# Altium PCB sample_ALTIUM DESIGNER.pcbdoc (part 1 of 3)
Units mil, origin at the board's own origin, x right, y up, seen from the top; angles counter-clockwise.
Board outline 2485.01 x 1905 mil, 6 copper layers (1 TallParts (2oz), 2 RTNS (2oz), 3 InternalPlane1 (2 oz), 4 InternalPlane2 (2 oz), 5 Signal (2oz), 6 LoParts (2oz)), stack 46.8 mil thick; 176 components, 89 nets, 769 pads, 0 vias.
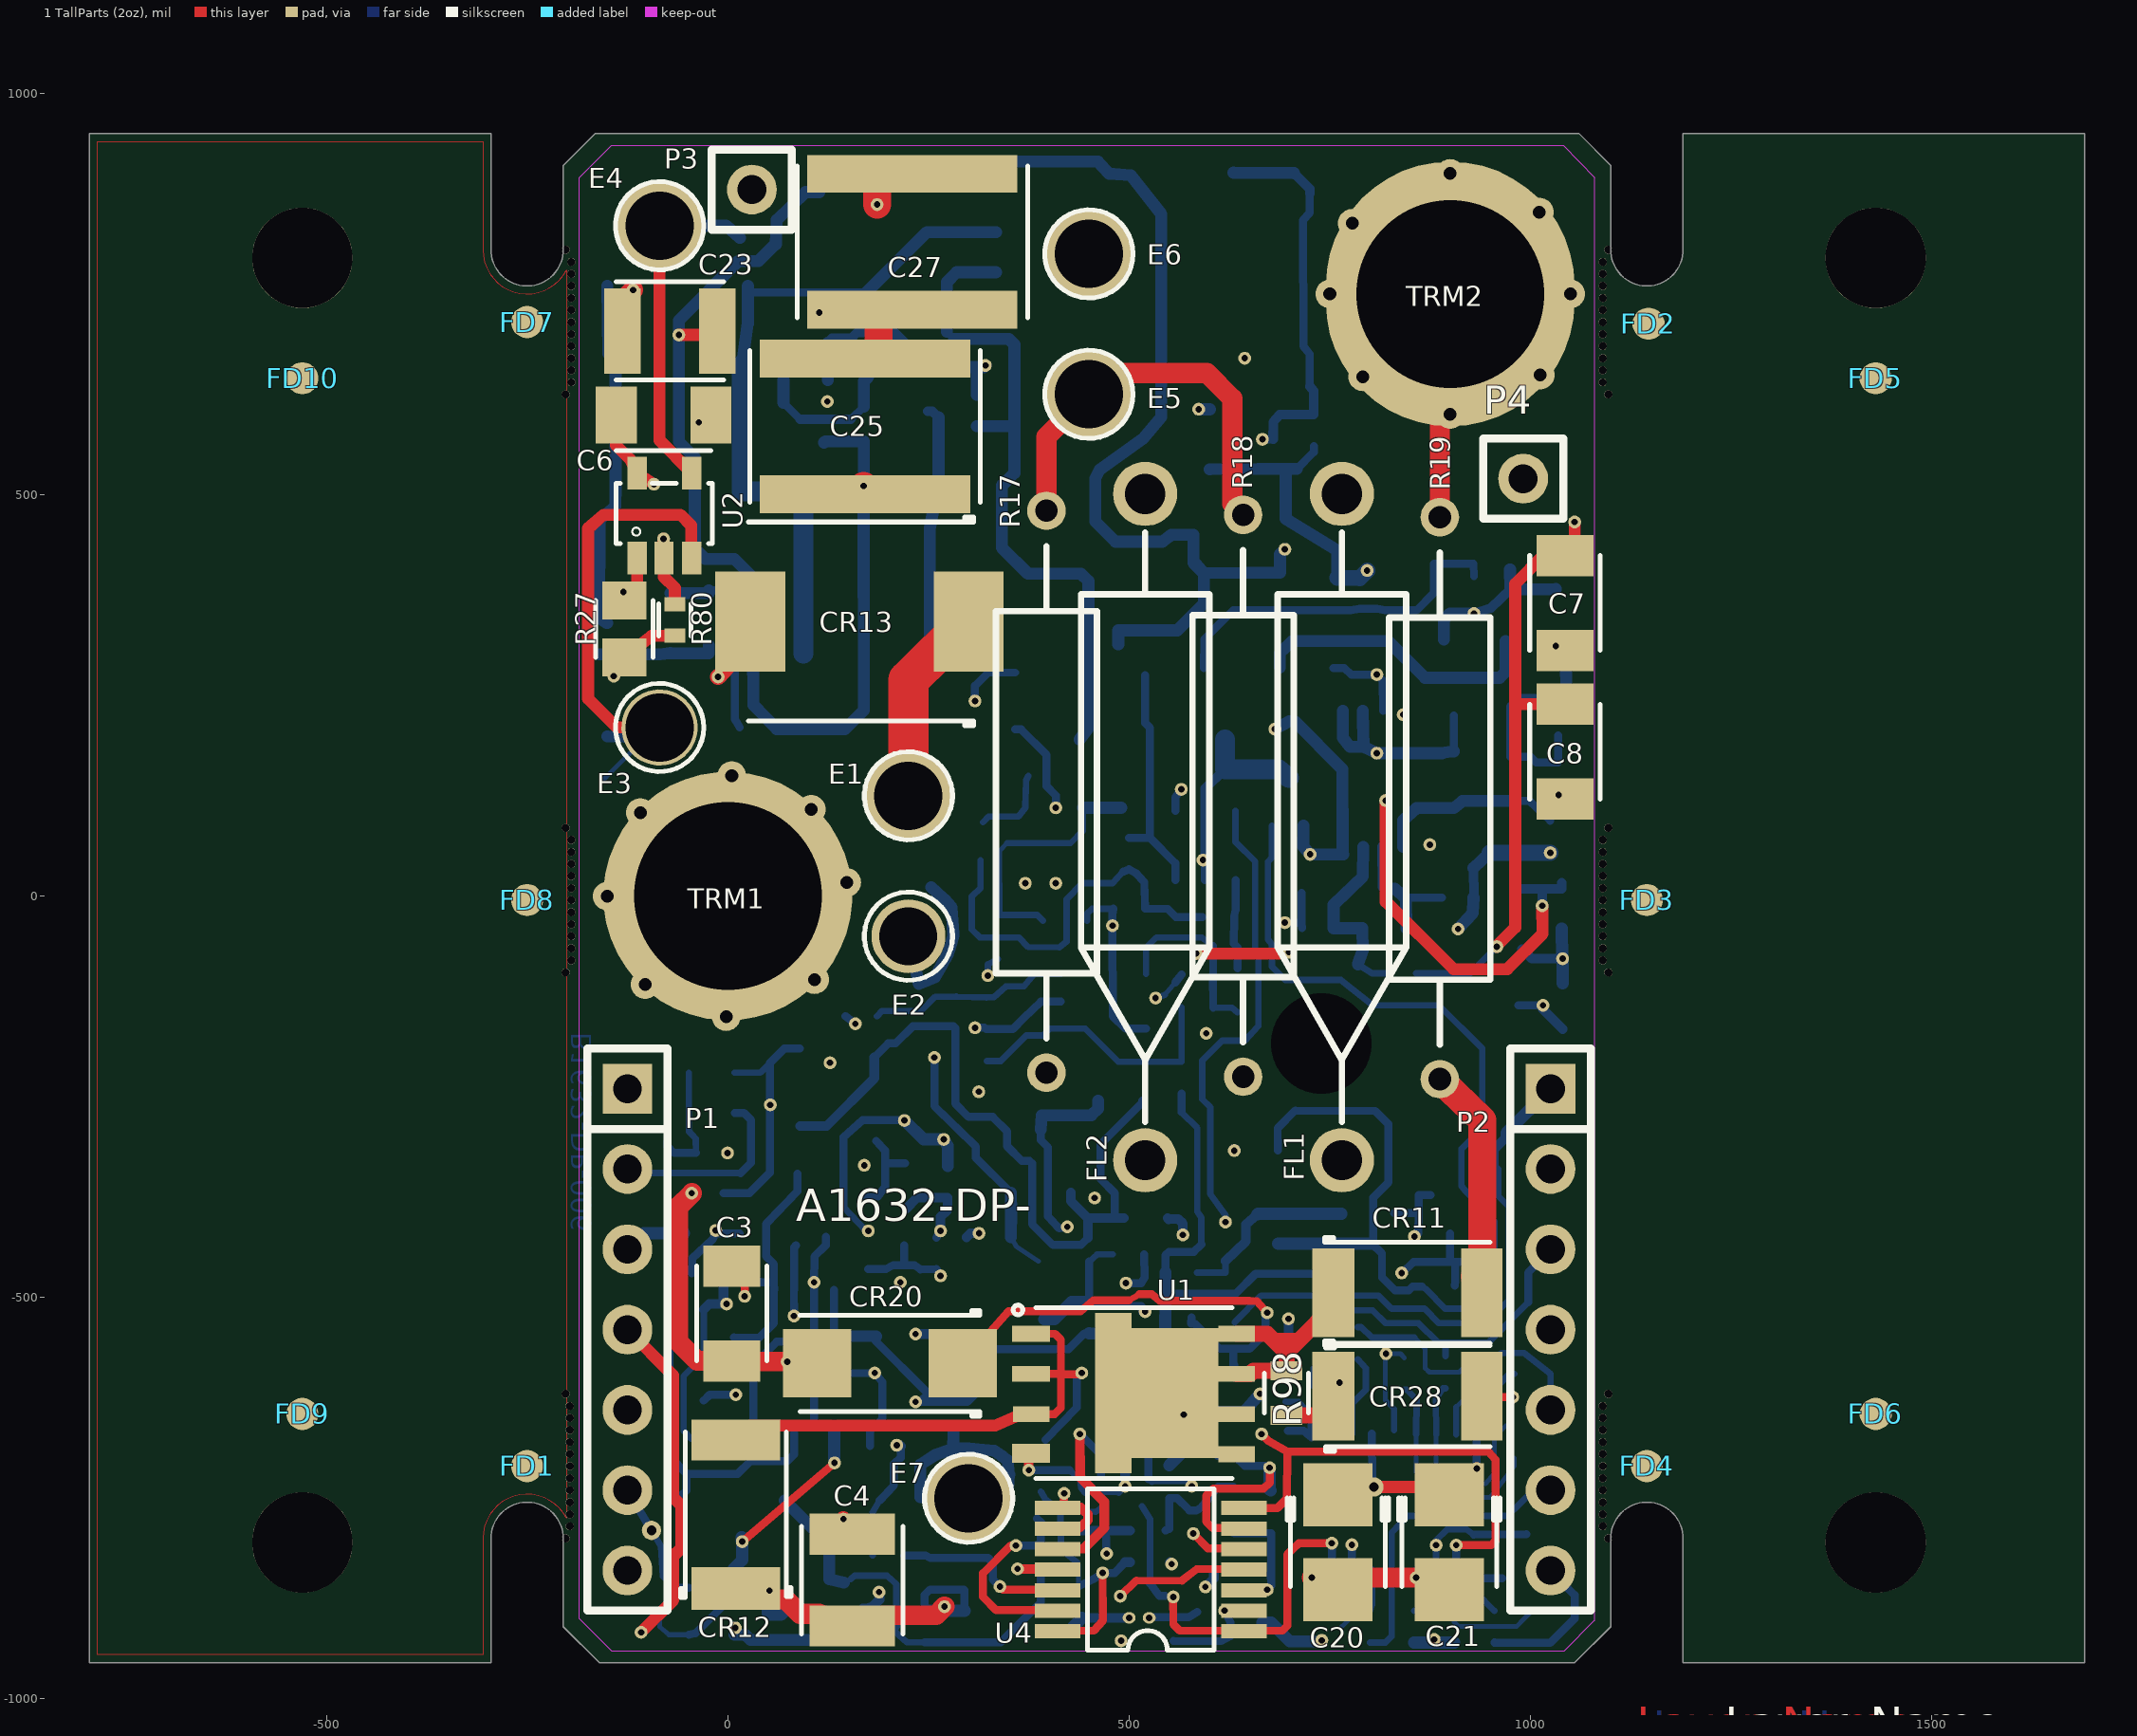
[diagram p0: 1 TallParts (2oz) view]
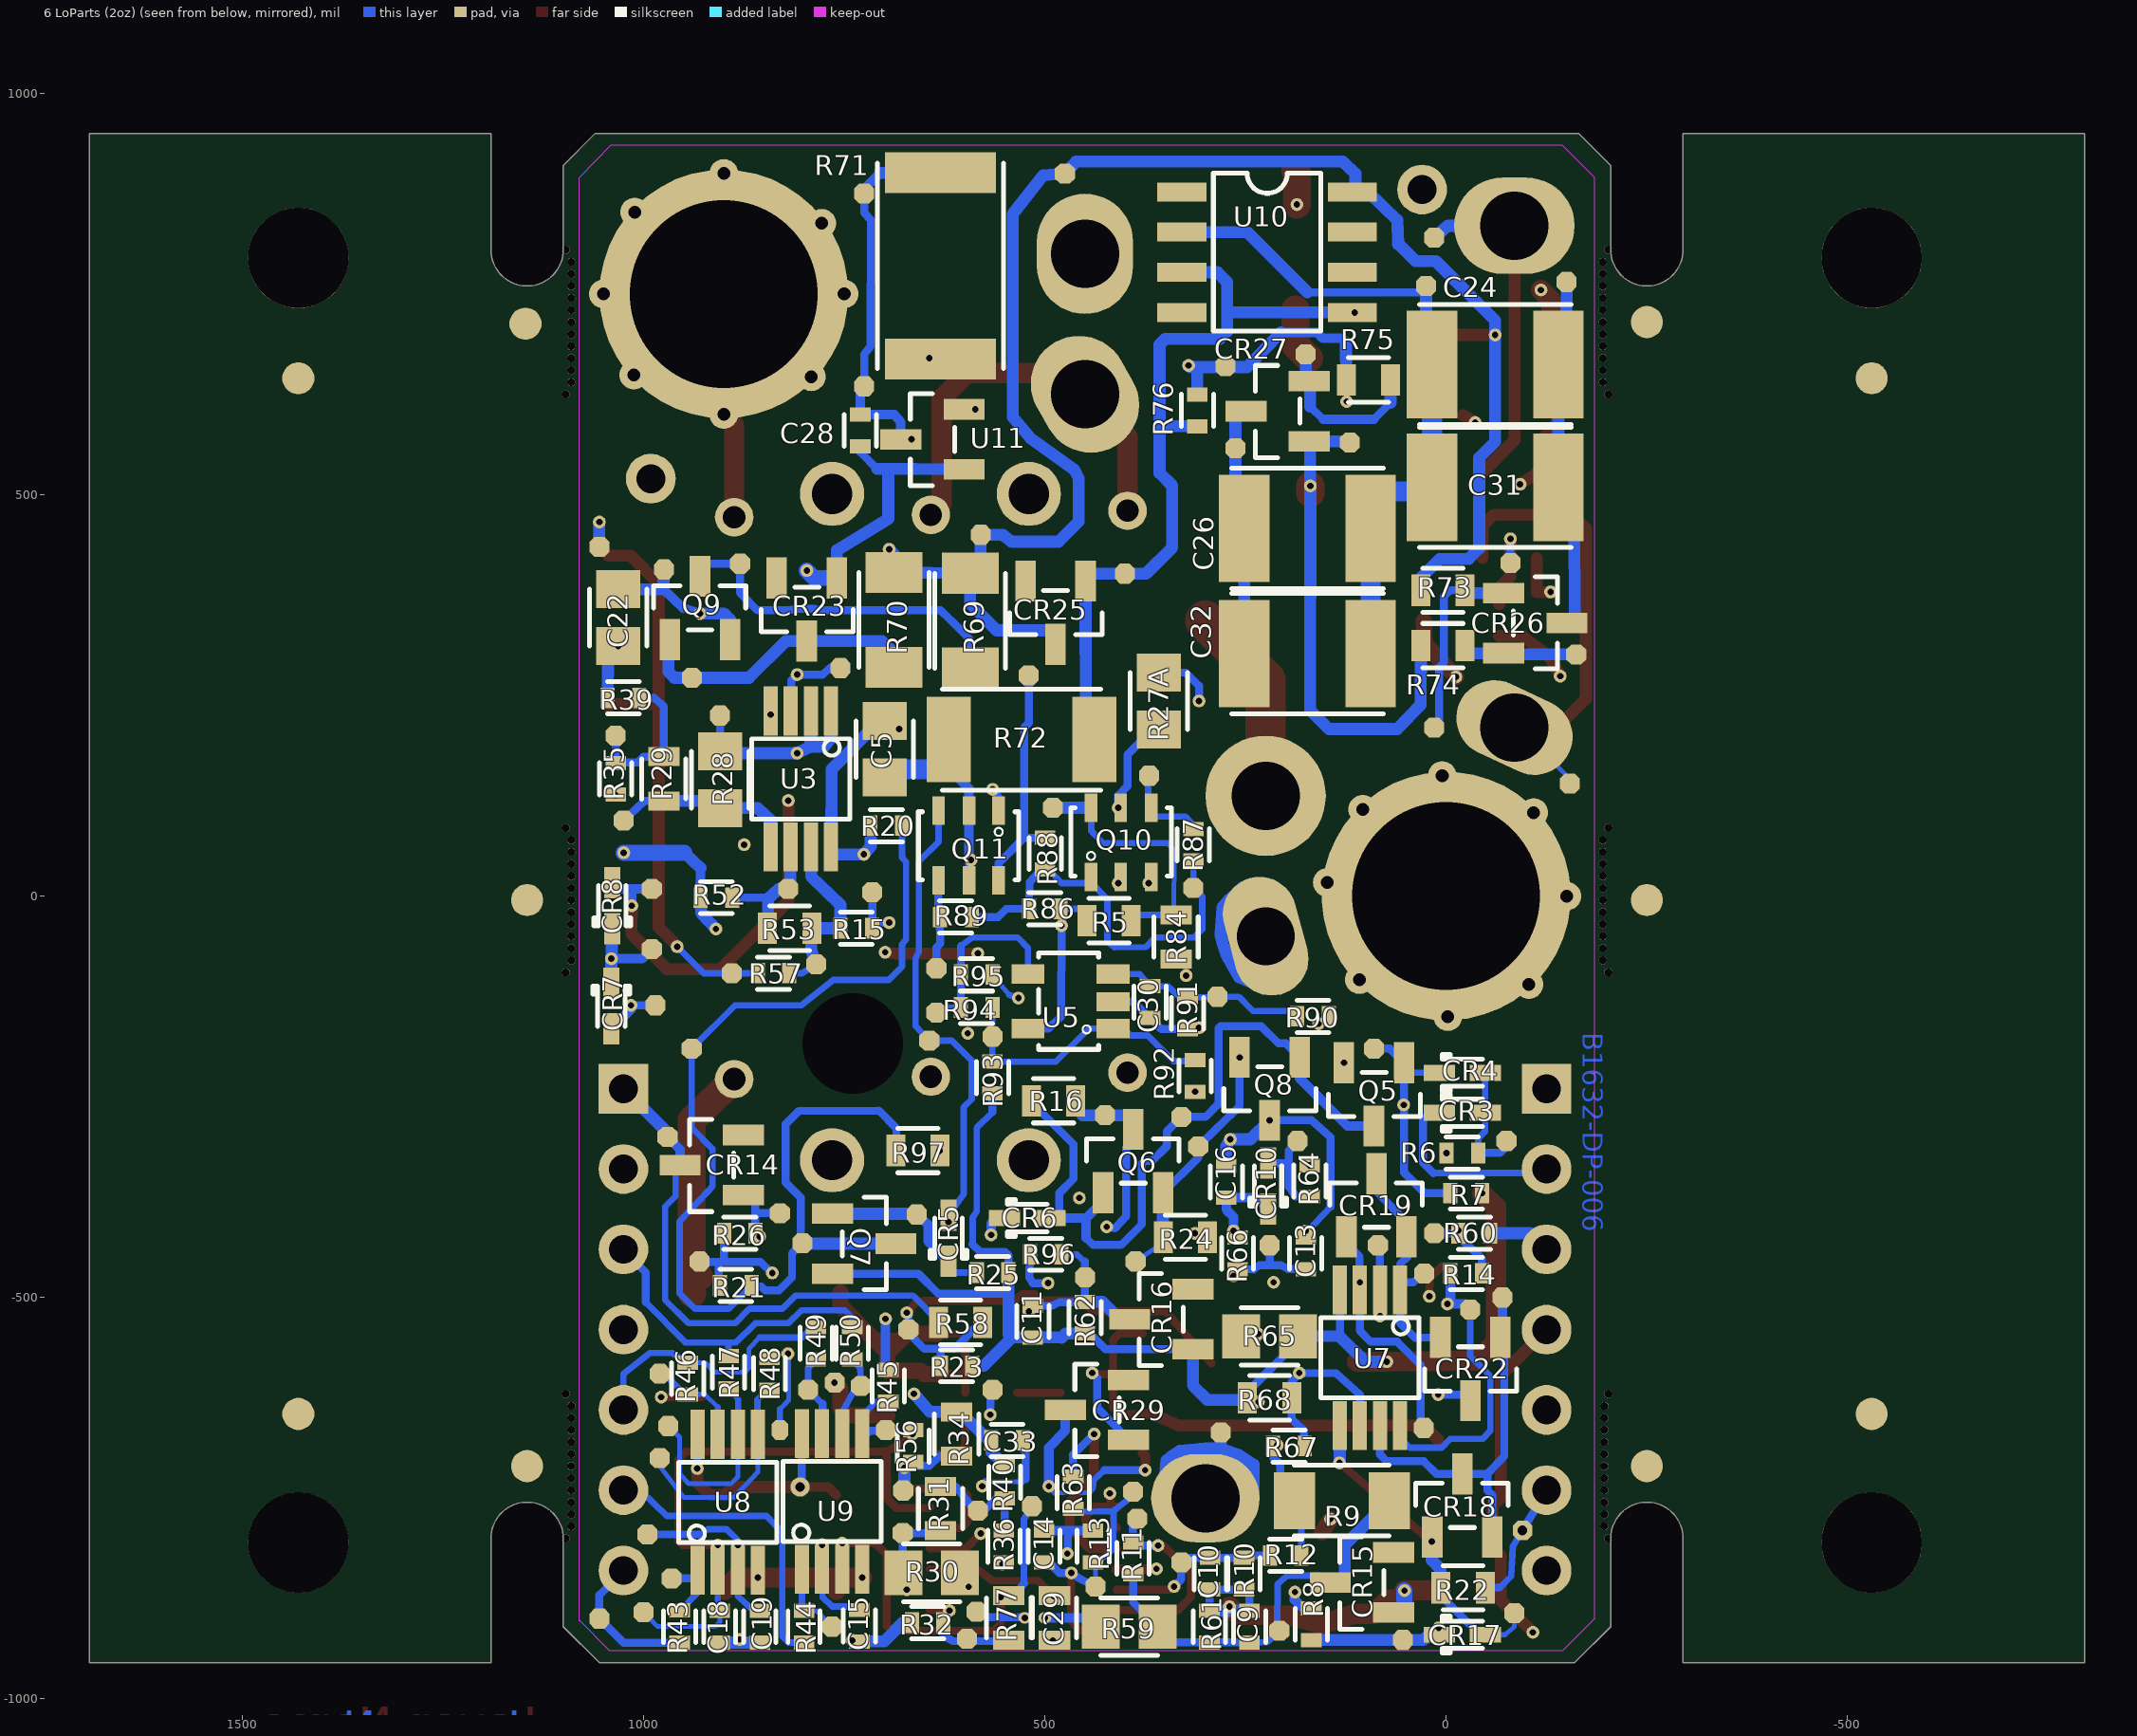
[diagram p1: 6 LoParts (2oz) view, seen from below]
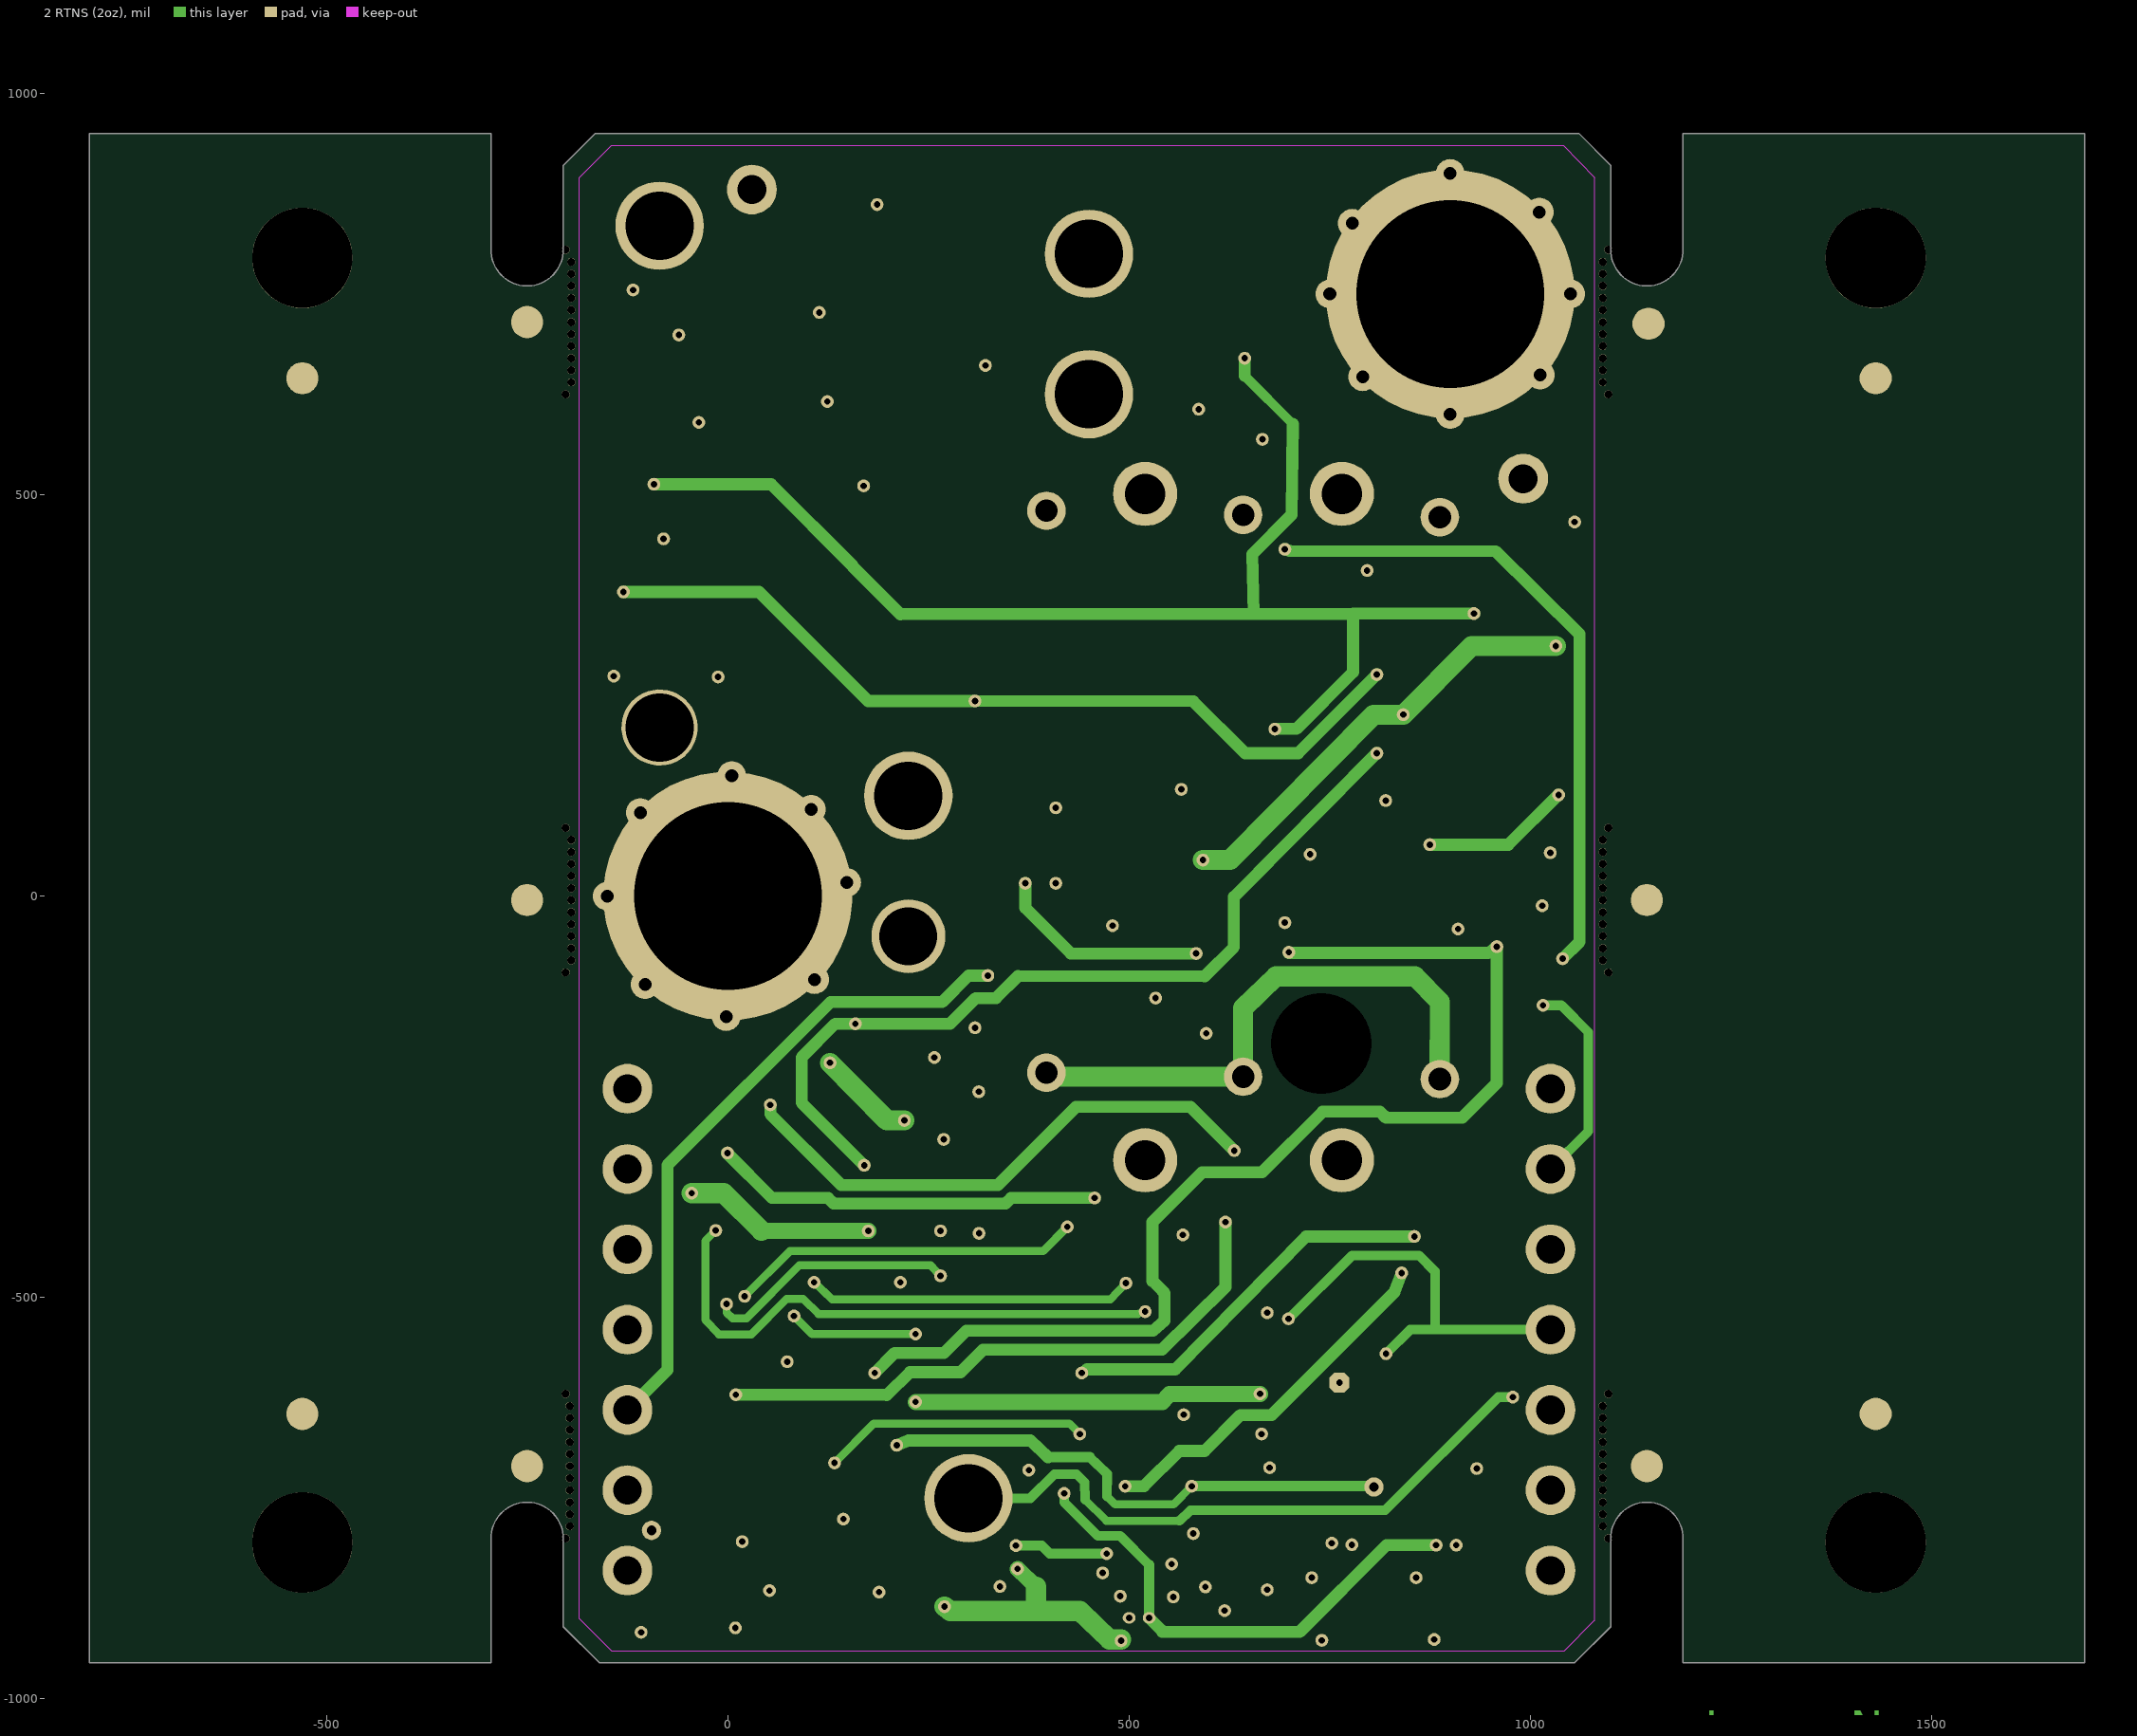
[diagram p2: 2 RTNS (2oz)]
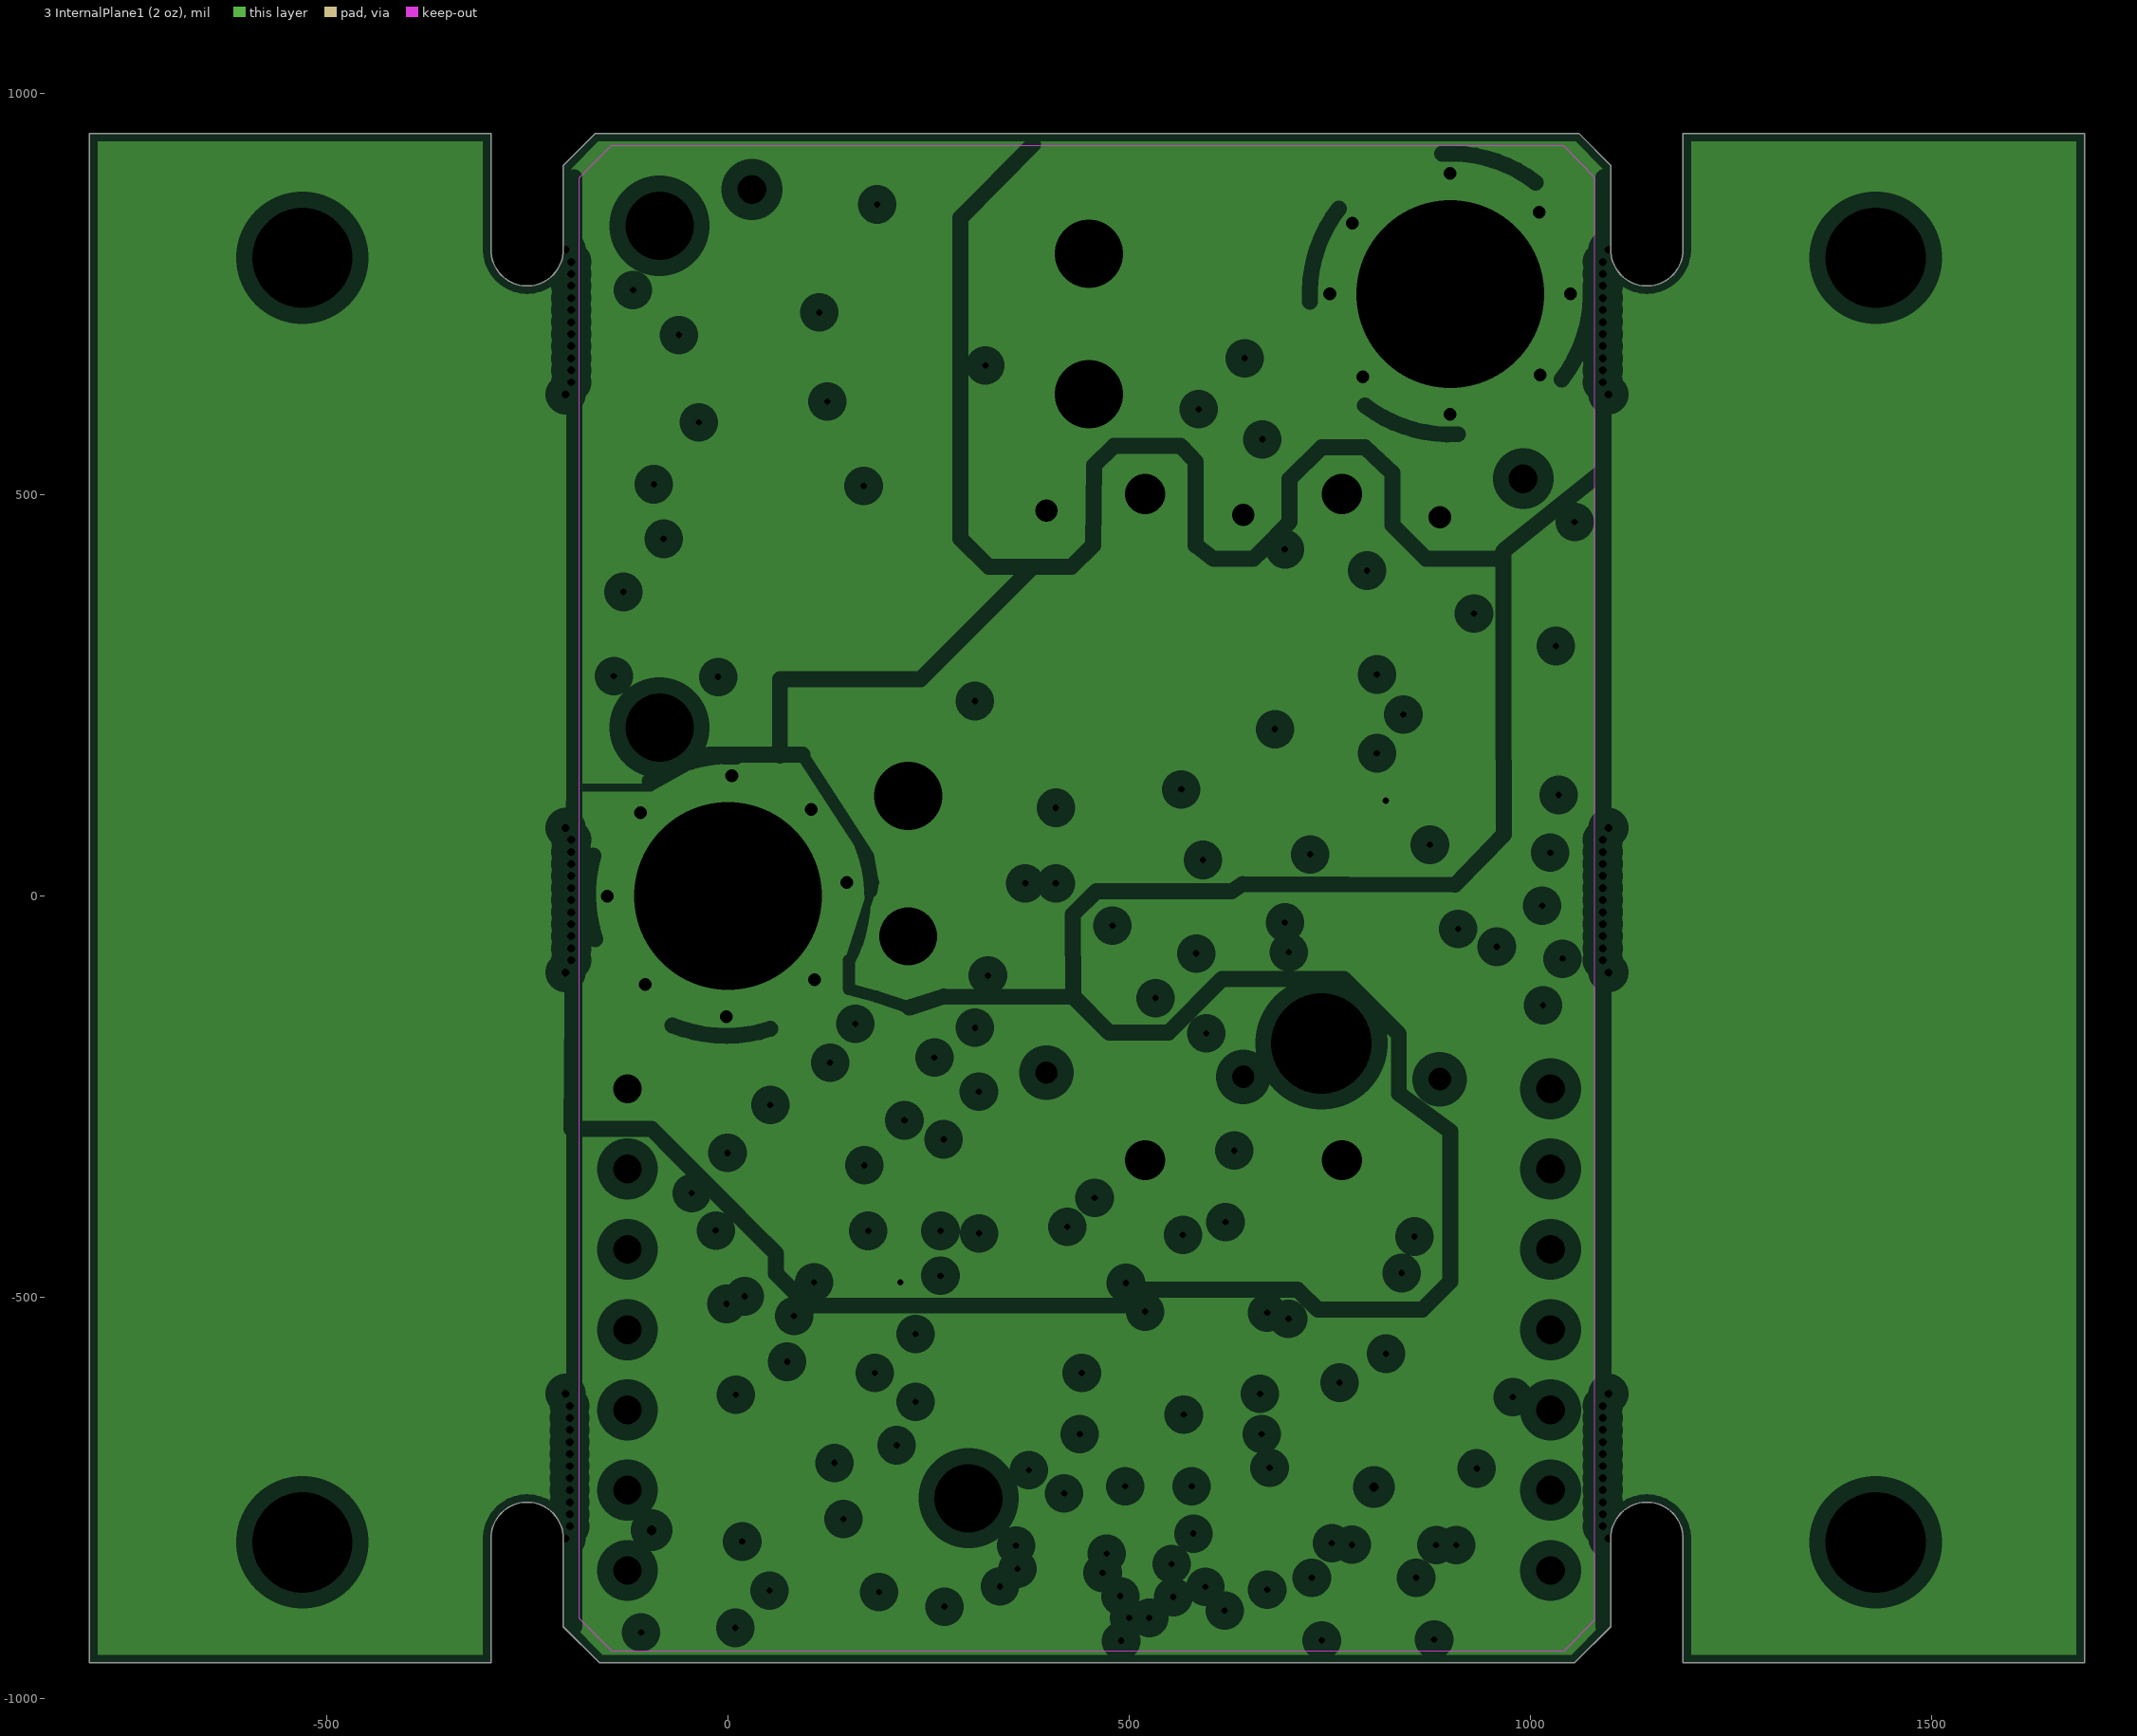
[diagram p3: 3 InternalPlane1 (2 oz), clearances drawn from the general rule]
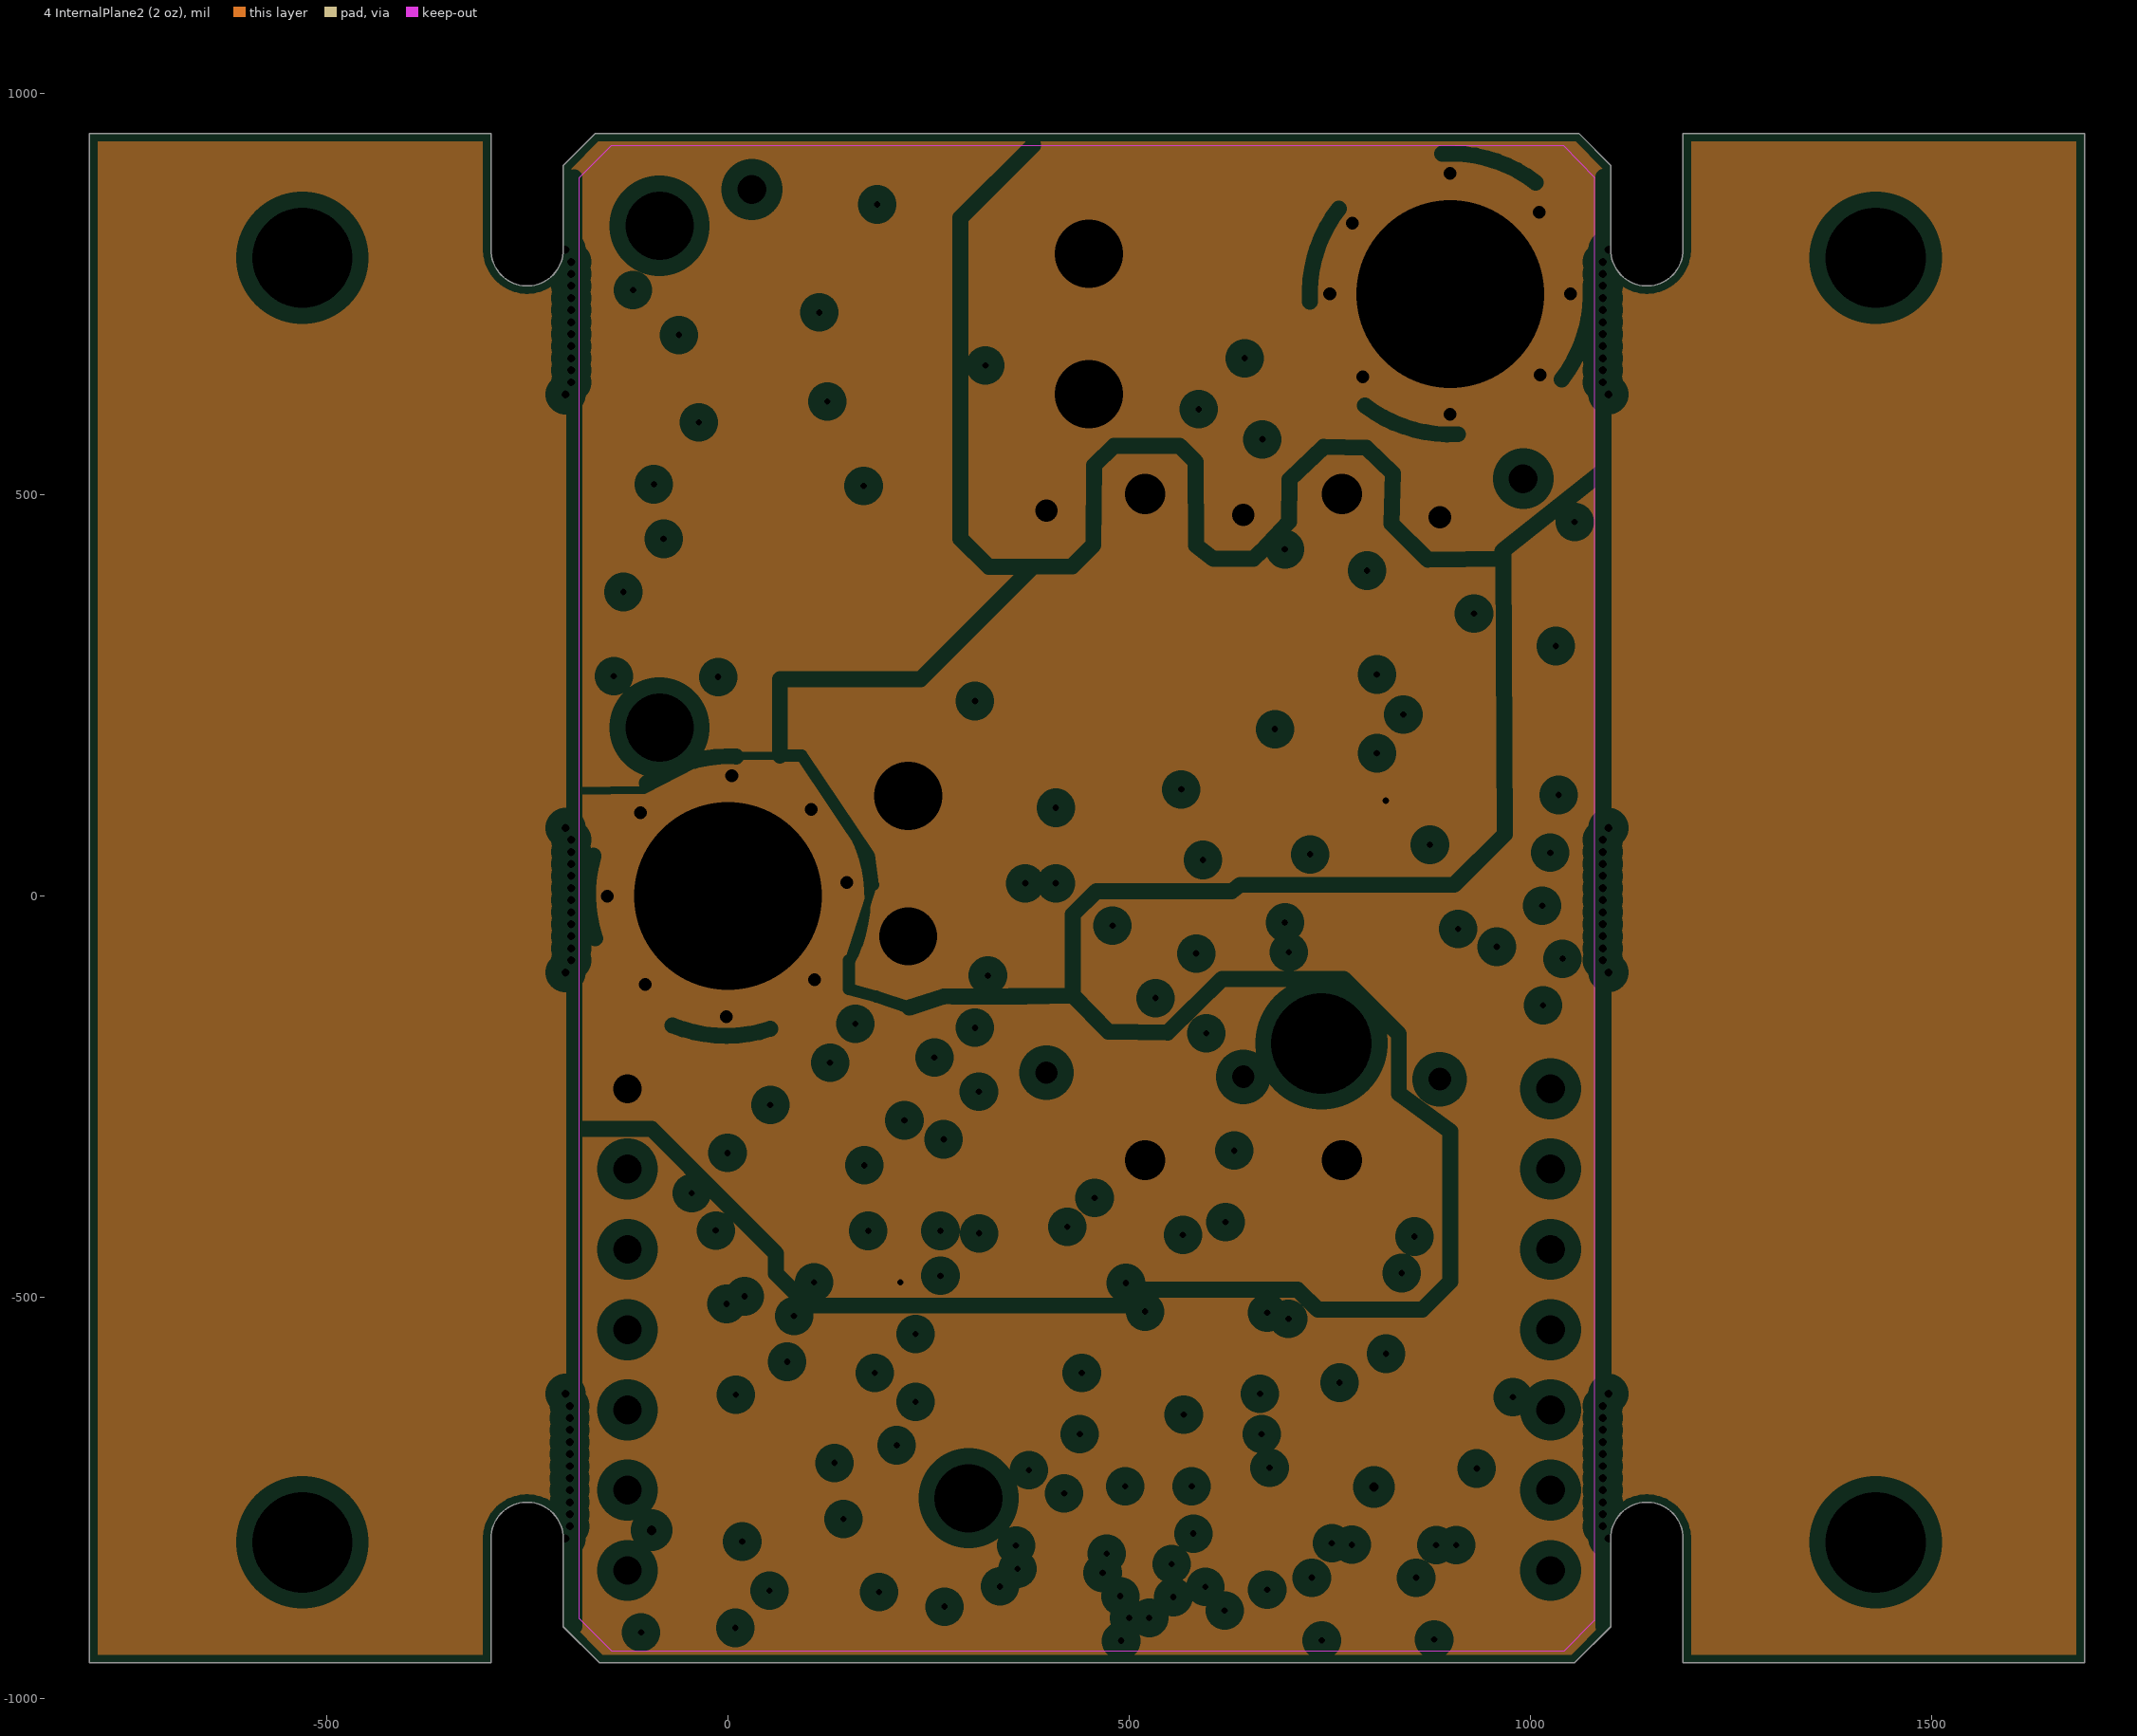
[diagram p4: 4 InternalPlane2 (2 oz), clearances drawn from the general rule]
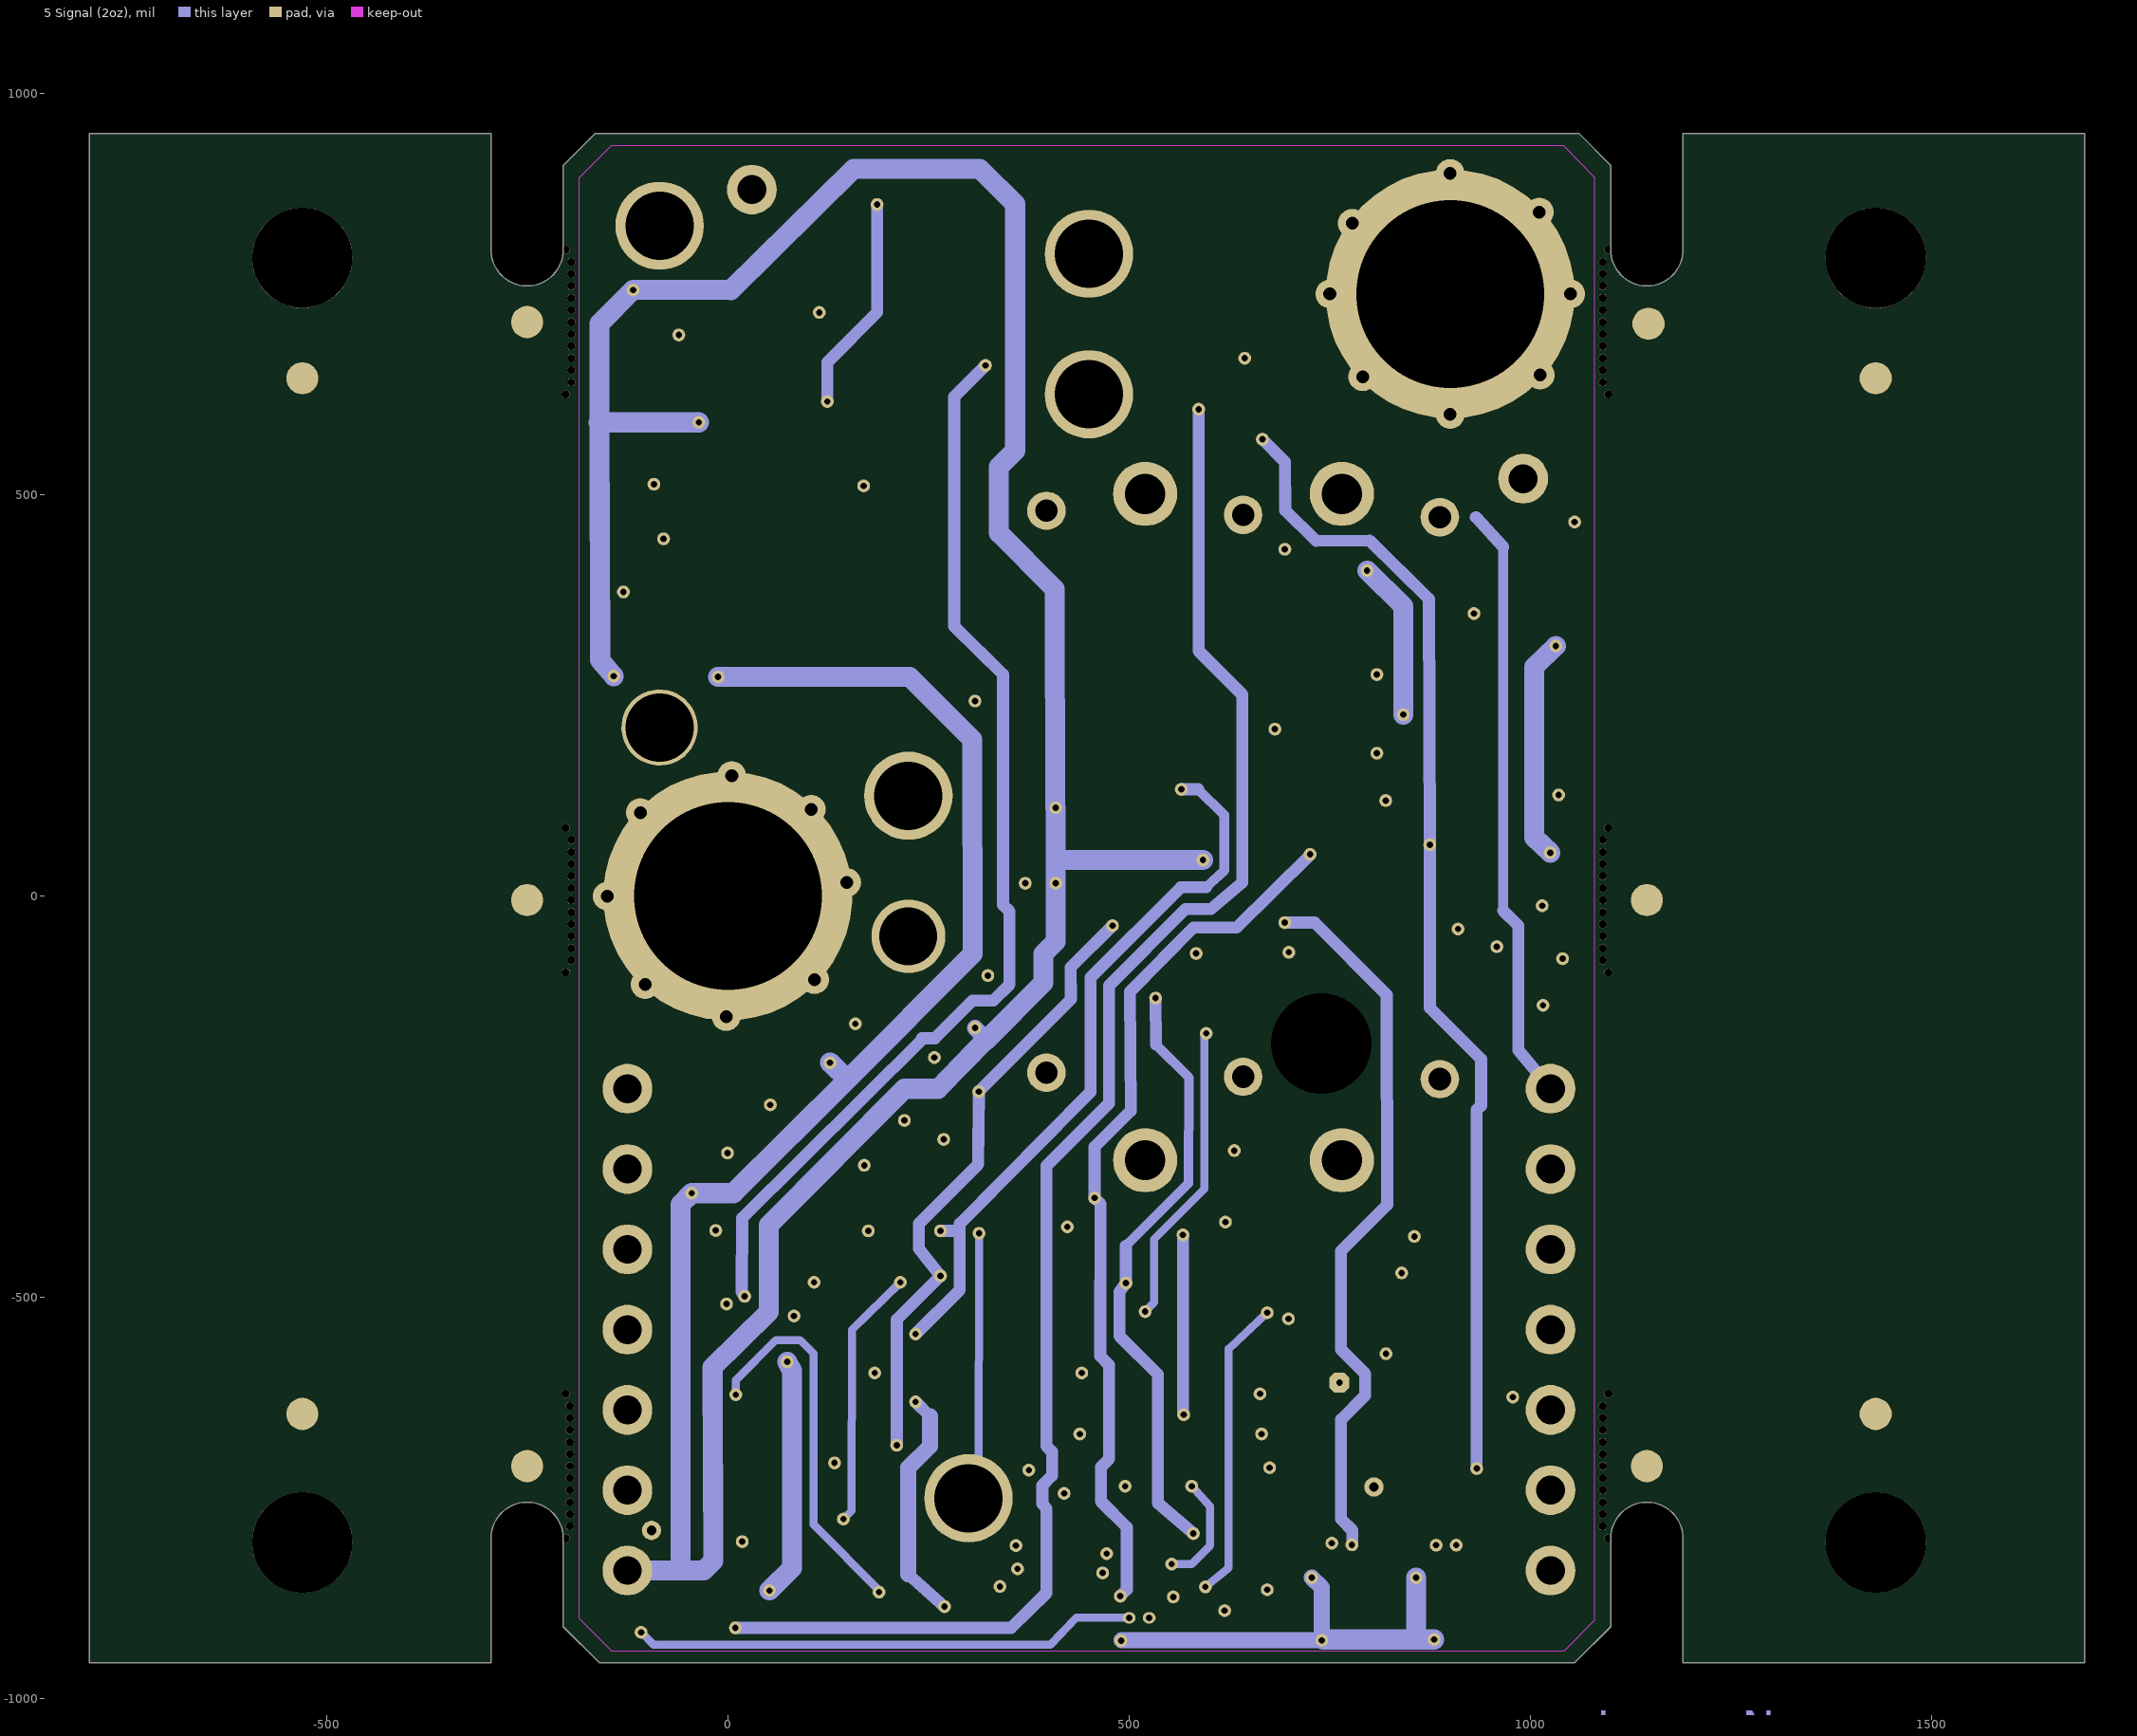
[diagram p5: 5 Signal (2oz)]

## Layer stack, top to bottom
1 TallParts (2oz): signal copper 2.8
Dielectric: core 6, FR-4, Dk 4.8
2 RTNS (2oz): signal copper 2.8
Dielectric: prepreg 6, FR-4, Dk 4.8
3 InternalPlane1 (2 oz): plane copper 2.8, net (Multiple Nets)
Dielectric: core 6, FR-4, Dk 4.8
4 InternalPlane2 (2 oz): plane copper 2.8, net (Multiple Nets)
Dielectric: prepreg 6, FR-4, Dk 4.8
5 Signal (2oz): signal copper 2.8
Dielectric: core 6, FR-4, Dk 4.8
6 LoParts (2oz): signal copper 2.8

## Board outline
-795,-954.96 -295,-954.96 -295,-799.96 cw(c-250,-799.96) -205,-799.96 -204.99,-799.96 -204.99,-910 -159.99,-955 1055.01,-955 1100.01,-910 1100.01,-799.96 1100,-799.96 cw(c1145,-799.96) 1190,-799.96 1190,-954.96 1190.01,-955 1690,-955 1690.01,950 1190,950 1190,805.04 cw(c1145,805.04) 1100,805.04 1100,910 1100.01,910 1060.03,950 -164.99,950 -204.99,910 -204.99,805 -205,805.04 cw(c-250,805.04) -295,805.04 -295,950 -795,950

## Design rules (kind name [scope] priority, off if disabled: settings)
Clearance TESTPOINTS [All] p0 off: scope1count=1 scope1_0_kind=Board scope1_0_value=Board scope2count=1 scope2_0_kind=Board scope2_0_value=Board commentlength=59 gap=8 // Protel DXP Scope 2 Expression Was: (InPadClass('ELSE'))
Clearance TESTPOINTS [(InPadClass('TESTPOINTS')) vs (InPadClass('ELSE'))] p1: scope1count=1 scope1_0_kind=Net scope1_0_value=28VA scope2count=1 scope2_0_kind=Net scope2_0_value=28VOUTPUT commentlength=0 gap=8
Clearance "KPOUT & ALL" [All vs (IsKeepOut)] p3: scope1count=1 scope1_0_kind=Board scope1_0_value=Board scope2count=1 scope2_0_kind=Board scope2_0_value=Board commentlength=0 planeconnectstyle=Direct reliefexpansion=20 reliefentries=4 reliefconductorwidth=10 reliefairgap="10mil / RECORD=DXPRule" gap=0
Clearance "MSOP-8/N - ALL" [(HasFootprint('MSOP-8/N') AND IsPad) vs (HasFootprint('MSOP-8/N') AND IsPad)] p4: scope1count=1 scope1_0_kind=Component scope1_0_value=FD6 scope2count=1 scope2_0_kind=Component scope2_0_value=TRM2 commentlength=0 gap=6
Clearance "28VA - 28VOUTPUT" [InNet('28VA') vs InNet('28VOUTPUT')] p5: scope1count=1 scope1_0_kind=Net scope1_0_value=28VA scope2count=1 scope2_0_kind=Net scope2_0_value=28VBUS commentlength=0 gap=20
Clearance "28VBUS - 28VA" [InNet('28VA') vs InNet('28VBUS')] p6: scope1count=1 scope1_0_kind=Net scope1_0_value=NetCR11_1 scope2count=1 scope2_0_kind=Net scope2_0_value=28VBUS commentlength=0 gap=20
Clearance E-POINTS [(HasFootprint('TERM832HEX250'))] p7: scope1count=1 scope1_0_kind=Board scope1_0_value=Board scope2count=1 scope2_0_kind=Board scope2_0_value=Board commentlength=0 connectstyle=Direct reliefconductorwidth=10 reliefentries=4 polygonreliefangle="90 Angle / RECORD=DXPRule" gap=16
Clearance "FL & HTRS" [InNet('NetCR11_1') vs InNet('28VBUS')] p8: scope1count=1 scope1_0_kind=Board scope1_0_value=Board scope2count=1 scope2_0_kind=Board scope2_0_value=Board commentlength=70 gap=16
Clearance "FD6 & TRM2" [InComponent('FD6') vs InComponent('TRM2')] p9: scope1count=1 scope1_0_kind=Component scope1_0_value=fd5 scope2count=1 scope2_0_kind=Component scope2_0_value=P1 commentlength=0 gap=8
Clearance "ALL ALL" [All] p10: scope1count=1 scope1_0_kind=Board scope1_0_value=Board scope2count=1 scope2_0_kind=Board scope2_0_value=Board commentlength=77 gap=8
Clearance "FD5 & P1" [InComponent('fd5') vs InComponent('P1')] p11: scope1count=1 scope1_0_kind=Net scope1_0_value=+38V scope2count=1 scope2_0_kind=Board scope2_0_value=Board commentlength=0 maxlimit=30 minlimit=8 preferedwidth="10mil / RECORD=DXPRule" gap=0
ComponentClearance "P1 - P2" [InComponent('P1') vs InComponent('P2')] p1: scope1count=1 scope1_0_kind=Board scope1_0_value=Board scope2count=1 scope2_0_kind=Board scope2_0_value=Board commentlength=0 clearance="20mil / RECORD=DXPRule" gap=0 collisioncheckmode=0 verticalgap=10
ComponentClearance [All] p2: scope1count=1 scope1_0_kind=Board scope1_0_value=Board scope2count=1 scope2_0_kind=Board scope2_0_value=Board commentlength=0 side=0 testpointundercomponent=FALSE minsize=25 maxsize=500 preferedsize=25 minholesize=12 maxholesize=12 preferedholesize=12 testpointgrid=5 style=231 order="0-112345678 / RECORD=DXPRule" gap=0 collisioncheckmode=0 verticalgap=10
FanoutControl Fanout_BGA [IsBGA] p1: scope1count=1 scope1_0_kind=Board scope1_0_value=Board scope2count=1 scope2_0_kind=Board scope2_0_value=Board commentlength=69 bgadir=Out bgaviamode=Centered fanoutstyle=Auto fanoutdirection=Alternating viagrid=1 // Fanout_BGA (Default Rule)
FanoutControl Fanout_LCC [IsLCC] p2: scope1count=1 scope1_0_kind=Board scope1_0_value=Board scope2count=1 scope2_0_kind=Board scope2_0_value=Board commentlength=71 bgadir=Out bgaviamode=Centered fanoutstyle=Auto fanoutdirection=Alternating viagrid=1 // Fanout_LCC (Default Rule)
FanoutControl Fanout_SOIC [IsSOIC] p3: scope1count=1 scope1_0_kind=Board scope1_0_value=Board scope2count=1 scope2_0_kind=Board scope2_0_value=Board commentlength=84 bgadir=Out bgaviamode=Centered fanoutstyle=Auto fanoutdirection=Alternating viagrid=1 // Fanout_SOIC (Default Rule)
FanoutControl Fanout_Small [(CompPinCount < 5)] p4: scope1count=1 scope1_0_kind=Board scope1_0_value=Board scope2count=1 scope2_0_kind=Board scope2_0_value=Board commentlength=30 bgadir=Out bgaviamode=Centered fanoutstyle=Auto fanoutdirection=OutThenIn viagrid=1 // Fanout_Small (Default Rule)
FanoutControl Fanout_Default [All] p5: scope1count=1 scope1_0_kind=Layer scope1_0_value=TOP scope2count=1 scope2_0_kind=Board scope2_0_value=Board commentlength=0 bgadir=Out bgaviamode=Centered fanoutstyle=Auto fanoutdirection=Alternating viagrid=1 // Fanout_Default (Default Rule)
Height Height_BOT [OnLayer('BottomLayer')] p1: scope1count=1 scope1_0_kind=Board scope1_0_value=Board scope2count=1 scope2_0_kind=Board scope2_0_value=Board commentlength=69 minheight=0 maxheight=60 prefheight=30
Height "Height TOP" [OnLayer('High Current')] p2: scope1count=1 scope1_0_kind=Pad scope1_0_value=Free-2 scope2count=1 scope2_0_kind=Board scope2_0_value=Board commentlength=0 expansion="-8mil / RECORD=DXPRule" minheight=0 maxheight=170 prefheight=150
HoleSize [All] p1: scope1count=1 scope1_0_kind=Board scope1_0_value=Board scope2count=1 scope2_0_kind=Board scope2_0_value=Board commentlength=0 enforce="FALSE / RECORD=DXPRule" absolutevalues=TRUE maxlimit=125 minlimit=0 maxpercent=80.000 minpercent=20.000
LayerPairs [All] p1: scope1count=1 scope1_0_kind=Board scope1_0_value=Board scope2count=1 scope2_0_kind=Board scope2_0_value=Board commentlength=0 gap=0 collisioncheckmode="0 / RECORD=DXPRule" enforce=FALSE
PasteMaskExpansion [All] p1: scope1count=1 scope1_0_kind=Board scope1_0_value=Board scope2count=1 scope2_0_kind=Board scope2_0_value=Board commentlength=0 holewidth=16 width=36 viastyle="Through Hole" minholewidth=16 minwidth=36 maxholewidth=16 maxwidth="36mil / RECORD=DXPRule" expansion=0
PlaneClearance [All] p1: scope1count=1 scope1_0_kind=Board scope1_0_value=Board scope2count=1 scope2_0_kind=Board scope2_0_value=Board commentlength=50 gap="0mil / RECORD=DXPRule" clearance=20
PlaneConnect [All] p1: scope1count=1 scope1_0_kind=Board scope1_0_value=Board scope2count=1 scope2_0_kind=Board scope2_0_value=Board commentlength=0 gap="8mil / RECORD=DXPRule" planeconnectstyle=Direct reliefexpansion=20 reliefentries=4 reliefconductorwidth=10 reliefairgap=10
PolygonConnect [All] p1: scope1count=1 scope1_0_kind=Layer scope1_0_value=TOP scope2count=1 scope2_0_kind=Board scope2_0_value=Board commentlength=0 connectstyle=Direct reliefconductorwidth=10 reliefentries=4 polygonreliefangle="90 Angle"
RoutingCorners [All] p1: scope1count=1 scope1_0_kind=Board scope1_0_value=Board scope2count=1 scope2_0_kind=Board scope2_0_value=Board commentlength=0 top layer=Vertical mid layer 2=Vertical mid layer 4=Vertical bottom layer="Horizontal / RECORD=DXPRule" cornerstyle=45-Degree minsetback=100 maxsetback=100
RoutingLayers [All] p1: scope1count=1 scope1_0_kind=Board scope1_0_value=Board scope2count=1 scope2_0_kind=Board scope2_0_value=Board commentlength=0 top layer_v5=TRUE mid layer 2_v5=TRUE mid layer 4_v5=TRUE bottom layer_v5=TRUE
RoutingPriority [All] p1: scope1count=1 scope1_0_kind=Board scope1_0_value=Board scope2count=1 scope2_0_kind=Board scope2_0_value=Board commentlength=0 maxlimit=800 minlimit=1 preferedwidth="30mil / RECORD=DXPRule" routingpriority=0
RoutingTopology [All] p1: scope1count=1 scope1_0_kind=Board scope1_0_value=Board scope2count=1 scope2_0_kind=Board scope2_0_value=Board commentlength=0 expansion="2mil / RECORD=DXPRule" topology=Shortest
RoutingVias [All] p1: scope1count=1 scope1_0_kind=Board scope1_0_value=Board scope2count=1 scope2_0_kind=Board scope2_0_value=Board commentlength=0 cornerstyle=45-Degree minsetback=100 maxsetback="100mil / RECORD=DXPRule" holewidth=16 width=36 viastyle="Through Hole" minholewidth=16 minwidth=36 maxholewidth=16 maxwidth=36
ShortCircuit [All] p1: scope1count=1 scope1_0_kind=Component scope1_0_value=P1 scope2count=1 scope2_0_kind=Component scope2_0_value=P2 commentlength=0 gap=0 collisioncheckmode="0 / RECORD=DXPRule" allowed=FALSE
SolderMaskExpansion SolderMaskExpansion_6 [HasPad('Free-2')] p1: scope1count=1 scope1_0_kind=Board scope1_0_value=Board scope2count=1 scope2_0_kind=Board scope2_0_value=Board commentlength=75 gap="6mil / RECORD=DXPRule" expansion=-8
SolderMaskExpansion [All] p2: scope1count=1 scope1_0_kind=Board scope1_0_value=Board scope2count=1 scope2_0_kind=Board scope2_0_value=Board commentlength=0 expansion=2
TestPointUsage [All] p1: scope1count=1 scope1_0_kind=Board scope1_0_value=Board scope2count=1 scope2_0_kind=Board scope2_0_value=Board commentlength=0 topology="Shortest / RECORD=DXPRule" valid=0 allowmultiple=TRUE
Testpoint [All] p1: scope1count=1 scope1_0_kind=Board scope1_0_value=Board scope2count=1 scope2_0_kind=Board scope2_0_value=Board commentlength=0 valid=0 allowmultiple="TRUE / RECORD=DXPRule" side=0 testpointundercomponent=FALSE minsize=25 maxsize=500 preferedsize=25 minholesize=12 maxholesize=12 preferedholesize=12 testpointgrid=5 style=231 order=0-112345678
UnRoutedNet [All] p1: scope1count=1 scope1_0_kind=Board scope1_0_value=Board scope2count=1 scope2_0_kind=Board scope2_0_value=Board commentlength=0 allowed="FALSE / RECORD=DXPRule"
Width Width_1 [InNet('NetCR17_2')] p1: scope1count=1 scope1_0_kind=Board scope1_0_value=Board scope2count=1 scope2_0_kind=Board scope2_0_value=Board commentlength=0 absolutevalues=TRUE maxlimit=20 minlimit=10 maxpercent=80.000 minpercent="20.000 / RECORD=DXPRule" preferedwidth=15
Width Width_13 [InNet('NetR10_2')] p2: scope1count=1 scope1_0_kind=Net scope1_0_value=NetCR6_2 scope2count=1 scope2_0_kind=Board scope2_0_value=Board commentlength=0 maxlimit=25 minlimit=15 preferedwidth=15
Width Width_3 [InNet('NetC8_1')] p3: scope1count=1 scope1_0_kind=Net scope1_0_value=NetU2_2 scope2count=1 scope2_0_kind=Board scope2_0_value=Board commentlength=0 maxlimit=20 minlimit=8 preferedwidth=10
Width Width_2 [InNet('NetU2_2')] p4: scope1count=1 scope1_0_kind=Net scope1_0_value=NetCR17_2 scope2count=1 scope2_0_kind=Board scope2_0_value=Board commentlength=0 maxlimit=20 minlimit=8 preferedwidth=15
Width Width_11 [InNet('NetCR7_3')] p5: scope1count=1 scope1_0_kind=Net scope1_0_value=28VOUTPUT scope2count=1 scope2_0_kind=Board scope2_0_value=Board commentlength=0 maxlimit=30 minlimit=10 preferedwidth=10
Width Width_7 [InNet('28VBUS')] p6: scope1count=1 scope1_0_kind=Net scope1_0_value=+20V scope2count=1 scope2_0_kind=Board scope2_0_value=Board commentlength=0 maxlimit=30 minlimit=10 preferedwidth=20
Width Width_12 [InNet('NetCR6_2')] p7: scope1count=1 scope1_0_kind=Net scope1_0_value=NetCR7_3 scope2count=1 scope2_0_kind=Board scope2_0_value=Board commentlength=0 maxlimit=30 minlimit=10 preferedwidth=25
Width Width_4 [InNet('GND')] p8: scope1count=1 scope1_0_kind=Net scope1_0_value=NetC8_1 scope2count=1 scope2_0_kind=Board scope2_0_value=Board commentlength=0 maxlimit=30 minlimit=10 preferedwidth=25 bottomlayer_prefwidth=10 minimp=50.000000 maximp=50.000000 favimp=50.000000
Width Width_10 [InNet('+38V')] p9: scope1count=1 scope1_0_kind=Net scope1_0_value=NetR10_2 scope2count=1 scope2_0_kind=Board scope2_0_value=Board commentlength=0 maxlimit=30 minlimit=8 preferedwidth=10
Width Width_6 [InNet('+20V')] p10: scope1count=1 scope1_0_kind=Net scope1_0_value=+5V scope2count=1 scope2_0_kind=Board scope2_0_value=Board commentlength=0 maxlimit=30 minlimit=8 preferedwidth=15
Width Width_5 [InNet('+5V')] p11: scope1count=1 scope1_0_kind=Net scope1_0_value=GND scope2count=1 scope2_0_kind=Board scope2_0_value=Board commentlength=0 maxlimit=30 minlimit=8 preferedwidth=10
Width Width_9 [InNet('28VOUTPUT')] p12: scope1count=1 scope1_0_kind=Net scope1_0_value=+28V scope2count=1 scope2_0_kind=Board scope2_0_value=Board commentlength=0 maxlimit=50 minlimit=8 preferedwidth=8 midlayer4_prefwidth=15 minimp=50.000000 maximp=50.000000 favimp=50.000000
Width Width_8 [InNet('+28V')] p13: scope1count=1 scope1_0_kind=Net scope1_0_value=28VBUS scope2count=1 scope2_0_kind=Board scope2_0_value=Board commentlength=0 maxlimit=300 minlimit=8 preferedwidth=15
Width [All] p14: scope1count=1 scope1_0_kind=Board scope1_0_value=Board scope2count=1 scope2_0_kind=Board scope2_0_value=Board commentlength=0 maxlimit=800 minlimit=1 preferedwidth=30 toplayer_prefwidth=20 midlayer2_prefwidth=15 midlayer4_prefwidth=15 bottomlayer_prefwidth=10 minimp=50.000000 maximp=50.000000 favimp=50.000000

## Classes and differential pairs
pad class TESTPOINTS: R71-1
pad class ELSE: C3-1 C3-2 C4-1 C4-2 C5-1 C5-2 C6-1 C6-2 C7-1 C7-2 C8-1 C8-2 C9-1 C9-2 C10-1 C10-2 C11-1 C11-2 C13-1 C13-2 C14-1 C14-2 C15-1 C15-2 C16-1 C16-2 C18-1 C18-2 C19-1 C19-2 C20-1 C20-2 C21-1 C21-2 C22-1 C22-2 C23-1 C23-2 C24-1 C24-2 C25-1 C25-2 C26-1 C26-2 C27-1 C27-2 C28-1 C28-2 C29-1 C29-2 C30-1 C30-2 C31-1 C31-2 C32-1 C32-2 C33-1 C33-2 CR3-1 CR3-2 CR4-1 CR4-2 CR5-1 CR5-2 CR6-1 CR6-2 CR7-1 CR7-2 CR8-1 CR8-2 CR10-1 CR10-2 CR11-1 CR11-2 CR12-1 CR12-2 CR13-1 CR13-2 CR14-1 CR14-2 CR14-3 CR15-1 CR15-2 CR15-3 CR16-1 CR16-2 CR16-3 CR17-1 CR17-2 CR18-1 CR18-2 CR18-3 CR19-1 CR19-2 CR19-3 CR20-1 CR20-2 CR22-1 CR22-2 CR22-3 CR23-1 CR23-2 CR23-3 CR24-1 CR24-2 CR25-1 CR25-2 CR25-3 CR26-1 CR26-2 CR26-3 CR27-1 CR27-2 CR27-3 CR28-1 CR28-2 CR29-1 CR29-2 CR29-3 E1-1 E2-1 E3-1 E4-1 E5-1 E6-1 E7-1 FD1-FD? FD2-FD? FD3-FD? FD4-FD5 FD5-FD? FD6-FD? FD7-FD? FD8-FD6 FD9-FD? FD10-FD? FL1-1 FL1-2 FL2-1 FL2-2 Free-0 Free-1 Free-4 Free-5 Free-9 P1-1 P1-2 P1-3 P1-4 P1-5 P1-6 P1-7 P2-1 P2-2 P2-3 P2-4 P2-5 P2-6 P2-7 Q5-1 Q5-2 Q5-3 Q6-1 Q6-2 Q6-3 Q7-1 Q7-2 Q7-3 Q8-1 Q8-2 Q8-3 Q9-1 Q9-2 Q9-3 Q10-1 Q10-2 Q10-3 Q10-4 Q10-5 Q10-6 Q11-1 Q11-2 Q11-3 Q11-4 Q11-5 Q11-6 R5-1 R5-2 R6-1 R6-2 R7-1 R7-2 R8-1 R8-2 R9-1 R9-2 R10-1 R10-2 R11-1 R11-2 R12-1 R12-2 R13-1 R13-2 R14-1 R14-2 R15-1 R15-2 R16-2 R17-1 R17-2 R18-1 R18-2 R19-1 R19-2 R20-1 R20-2 R21-1 R21-2 R22-1 R22-2 R23-1 R23-2 R24-1 R24-2 R25-1 R25-2 R26-1 R26-2 R27-1 R27-2 R27A-1 R27A-2 R28-1 R28-2 R29-1 R29-2 R30-1 R30-2 R31-1 R31-2 R32-1 R32-2 R34-1 R34-2 R35-1 R35-2 R36-1 R36-2 R39-1 R39-2 R40-1 R40-2 R43-1 R43-2 R44-1 R44-2 R45-1 R45-2 R46-1 R46-2 R47-1 R47-2 R48-1 R48-2 R49-1 R49-2 R50-1 R50-2 R52-1 R52-2 R53-1 R53-2 R56-1 R56-2 R57-1 R57-2 R58-1 R58-2 R59-1 R59-2 R60-1 R60-2 R61-1 R61-2 R62-1 R62-2 R63-1 R63-2 R64-1 R64-2 R65-1 R65-2 R66-1 R66-2 R67-1 R67-2 R68-1 R68-2 R69-1 R69-2 R70-1 R70-2 R71-1 R71-2 R72-1 R72-2 R73-1 R73-2 R74-1 R74-2 R75-1 R75-2 R76-1 R76-2 R77-1 R77-2 R80-1 R80-2 R84-1 R84-2 R86-1 R86-2 R87-1 R87-2 R88-1 R88-2 R89-1 R89-2 R90-1 R90-2 R91-1 R91-2 R92-1 R92-2 R93-1 R93-2 R94-1 R94-2 R95-1 R95-2 R96-1 R96-2 R97-2 TRM1-1 TRM2-1 U1-1 U1-2 U1-3 U1-4 U1-5 U1-6 U1-7 U1-8 U2-1 U2-2 U2-3 U2-4 U2-5 U3-1 U3-2 U3-3 U3-4 U3-5 U3-6 U3-7 U3-8 U4-1 U4-2 U4-3 U4-4 U4-5 U4-6 U4-7 U4-8 U4-9 U4-10 U4-11 U4-12 U4-13 U4-14 U5-1 U5-2 U5-3 U5-4 U5-5 U7-1 U7-2 U7-3 U7-4 U7-5 U7-6 U7-7 U7-8 U8-1 U8-2 U8-3 U8-4 U8-5 U8-6 U8-7 U8-8 U9-1 U9-2 U9-3 U9-4 U9-5 U9-6 U9-7 U9-8 U10-1 U10-2 U10-3 U10-4 U10-5 U10-6 U10-7 U10-8 U11-1 U11-2 U11-3
component class S1632DP06_1_0A: C9 C10 C11 C13 C14 C15 C16 C18 C19 C20 C21 C22 C23 C24 C25 C26 C27 C28 C29 C30 C31 C32 C33 CR7 CR8 CR10 CR15 CR16 CR17 CR18 CR19 CR20 CR22 CR23 CR25 CR26 CR27 FD1 FD2 FD3 FD4 FD5 FD6 FD7 FD8 FD9 FD10 FD15 FD16 P1 P2 P3 P4 Q9 Q10 Q11 R5 R9 R10 R11 R12 R13 R14 R15 R22 R23 R30 R31 R32 R34 R36 R40 R43 R44 R45 R46 R47 R48 R49 R50 R56 R58 R59 R60 R61 R62 R63 R64 R65 R66 R67 R68 R69 R70 R71 R72 R73 R74 R75 R76 R77 R84 R86 R87 R88 R89 R90 R91 R92 R93 R94 R95 R96 U4 U5 U7 U8 U9 U10 U11
component class S1632DP06_2_0A: C1 C2 C3 C4 C5 C6 C7 C8 CR1 CR2 CR3 CR4 CR5 CR6 CR11 CR12 CR13 CR14 CR28 CR29 E1 E2 E3 E4 E5 E6 E7 FL1 FL2 J1 J2 J3 J4 J5 J6 J7 Q1 Q2 Q3 Q4 Q5 Q6 Q7 Q8 R1 R2 R3 R4 R6 R7 R8 R16 R17 R18 R19 R20 R21 R24 R25 R26 R27 R27A R28 R29 R35 R39 R52 R53 R57 R80 R97 R98 TRM1 TRM2 U1 U2 U3

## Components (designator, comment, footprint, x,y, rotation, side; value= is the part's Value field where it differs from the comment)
C3 "223-101-10CX1206" 1206/N 5.01,-520 r270 top
C4 "105-101-10CX1210" 1210/N#1 155.01,-852 r270 top
C5 "104-50V-10CX0805" 0805/N#1 699.6,183 r270 bottom
C6 "105-100V-10CX1206" 1206/N -80,599 r0 top
C7 "225-16V-10CX1206" 1206/N 1043,365 r270 top
C8 "225-16V-10CX1206" 1206/N 1043,180 r270 top
C9 "104-10V-10CX0402" 0402/0.60/N 245.01,-910 r90 bottom
C10 "104-10V-10CX0402" 0402/0.60/N 294,-844 r270 bottom
C11 "104-10V-10CX0402" 0402/0.60/N 515.01,-530 r270 bottom
C13 "103-16V-10CX0402" 0402/0.60/N 175.01,-445 r90 bottom
C14 "101-10V-5#NX0402" 0402/0.60/N 501,-810 r270 bottom
C15 "101-10V-5#NX0402" 0402/0.60/N 731.01,-909 r270 bottom
C16 "104-10V-10CX0402" 0402/0.60/N 274,-356 r90 bottom
C18 "102-25V-5#CX0402" 0402/0.60/N 905.01,-910 r270 bottom
C19 "102-25V-5#CX0402" 0402/0.60/N 855.01,-910 r270 bottom
C20 "475-20V-10TX3528" 3528/N 760.01,-805 r90 top
C21 "475-20V-10TX3528" 3528/N 899,-805 r90 top
C22 "104-50V-10CX0805" 0805/N#1 1031.61,347 r270 bottom
C23 "105-101-10CX1210" 1210/N#2 -72,704 r180 top
C24 "474-50V-10CX1812" 1812/N -61,662 r0 bottom
C25 "684-101-10CX1825" 1825/2.18/N 171,585 r90 top
C26 "474-50V-10CX1812" 1812/N 173,458 r180 bottom
C27 "684-101-10CX1825" 1825/2.18/N 230,815 r270 top
C28 "104-10V-10CX0402" 0402/0.60/N 730,580 r270 bottom
C29 "103-50V-10CX0603" 0603/0.90/N 488,-899 r270 bottom
C30 "101-10V-5#NX0402" 0402/0.60/N 369,-132 r270 bottom
C31 "474-50V-10CX1812" 1812/N -61,509 r0 bottom
C32 "474-50V-10CX1812" 1812/N 173,302 r180 bottom
C33 "103-16V-10CX0402" 0402/0.60/N 547,-678 r180 bottom
CR3 "D80V0_I10__X" SC-79/N -19.99,-270 r270 bottom
CR4 "D80V0_I10__X" SC-79/N -19.99,-220 r270 bottom
CR5 "D80V0_I10__X" SC-79/N 620,-426 r180 bottom
CR6 "D80V0_I10__X" SC-79/N 522,-401 r270 bottom
CR7 "D80V0_I10__X" SC-79/N 1040,-137 r0 bottom
CR8 "D80V0_I10__X" SC-79/N 1039,-12 r180 bottom
CR10 "D80V0_I10__X" SC-79/N 222,-361 r180 bottom
CR11 "D40V0_1I0_X" MLL41/N 847,-494 r180 top
CR12 "D40V0_1I0_X" MLL41/N 10.01,-770 r270 top
CR13 "Z75V0U3W0KZX" DO-214AB/N 166,342 r0 top
CR14 "D70V0_I10_X" SOT-23/N 915,-335 r90 bottom
CR15 "Z12V0UW300GX" SOT-23/N 105,-855 r90 bottom
CR16 "Z12V0UW300GX" SOT-23/N 355,-527 r90 bottom
CR17 "D30V0_I15S_X" SC-79/N -19.99,-920 r270 bottom
CR18 "D75V0SI16__X" SOT-23/N -20,-759 r180 bottom
CR19 "D75V0SI16__X" SOT-23/N 87,-385 r180 bottom
CR20 "Z12V0U1W00JX" SMA/N 202,-582 r180 top
CR22 "D70V0AI07S_X" SOT-23/N -30,-589 r0 bottom
CR23 "Z20V0UW300JX" SOT-23/N 796.61,357 r0 bottom locked
CR25 "Z12V0UW300GX" SOT-23/N 486.61,353 r0 bottom
CR26 "D75V0SI16__X" SOT-23/N -111,340 r270 bottom
CR27 "D75V0SI16__X" SOT-23/N 210,604 r90 bottom locked
CR28 "Comment" MLL41/N 847,-623 r180 top
CR29 "Z12V0UW300GX" SOT-23/N 435,-640 r90 bottom
E1 "E PAD, 100RD76P" TP-100#1 225.01,125 r0 top locked
E2 "E PAD, 100RD76P" TP-100#2 225.01,-50 r0 top locked
E3 "E PAD, 100RD76P" TP-100#3 -84.99,210 r0 top locked
E4 "E PAD, 100RD76P" TP-100#4 -84.99,835 r0 top locked
E5 "E PAD, 100RD76P" TP-100#5 450.01,625 r0 top locked
E6 "E PAD, 100RD76P" TP-100#5 450.01,800 r0 top locked
E7 "E PAD, 100RD76P" TP-100#6 300.01,-750 r0 top locked
FD1 "FIDUCIAL" FIDUCIAL_X#1 -250,-710 r0 top locked
FD2 "FIDUCIAL" FIDUCIAL_X#1 1147,713 r0 top locked
FD3 "FIDUCIAL" FIDUCIAL_X#1 1145,-5 r0 top locked
FD4 "FIDUCIAL" FIDUCIAL_X#2 1145,-710 r0 top locked
FD5 "FIDUCIAL" FIDUCIAL_X#1 1430,645 r0 top locked
FD6 "FIDUCIAL" FIDUCIAL_X#1 1430,-645 r0 top locked
FD7 "FIDUCIAL" FIDUCIAL_X#1 -250,715 r0 top locked
FD8 "FIDUCIAL" FIDUCIAL_X#3 -250,-5 r0 top locked
FD9 "FIDUCIAL" FIDUCIAL_X#1 -530,-645 r0 top locked
FD10 "FIDUCIAL" FIDUCIAL_X#1 -530,645 r0 top locked
FL1 "25A_152C_CUTOFF" AX.83/.158FL 765,-329 r90 top locked
FL2 "25A_152C_CUTOFF" AX.83/.158FL 520,-329 r90 top
P1 "7P ST LHDR 100(2X)" SIP7 -124.99,-240 r270 top locked
P2 "7P ST LHDR 100(2X)" SIP7 1025,-240 r270 top locked
P3 "*" SIP1 30,880 r0 top
P4 "*" SIP1 991,520 r0 top
Q5 "TNP300V_I50X" SOT-23/N 90.01,-247 r0 bottom
Q6 "TNP300V_I50X" SOT-23/N 390,-330 r180 bottom
Q7 "TNP300V_I50X" SOT-23/N 725,-433 r270 bottom locked
Q8 "TPN300V_I20X" SOT-23/N 220.01,-240 r0 bottom
Q9 "TNP300V_I50X" SOT-23/N 929.6,359 r180 bottom
Q10 "TNP50V0_1I0ZX" SOT-23-6/N 405,67 r0 bottom
Q11 "TNP50V0_1I0ZX" SOT-23-6/N 595,63 r180 bottom
R5 "R100K0D1#0GX0603" 0603/N#1 420,-30 r0 bottom
R6 "R20K00D1#0HX0402" 0402/N#1 -19.99,-320 r0 bottom
R7 "R4K700D1#0HX0402" 0402/N#1 -24.99,-370 r0 bottom
R8 "R34K80D1#0HX0402" 0402/N#1 168,-907 r270 bottom
R9 "R100K0D1#0BX1206" 1206/N 130,-753 r0 bottom
R10 "R45K30D1#0HX0402" 0402/N#1 252,-844 r90 bottom
R11 "R100K0D1#0HX0402" 0402/N#1 390.01,-825 r270 bottom
R12 "R86K60D1#0HX0402" 0402/N#2 200,-821 r0 bottom
R13 "R100K0D1#0HX0402" 0402/N#1 440,-810 r270 bottom
R14 "R100K0D1#0HX0402" 0402/N#1 -24.99,-470 r0 bottom
R15 "R1K000D1#0HX0402" 0402/N#1 735,-40 r180 bottom
R16 "R38K30D1#0GX0603" 0603/N#2 489,-255 r180 bottom
R17 "R68R00E1#0EW" "AX.7/.125 CTRD" 397,480 r270 top locked
R18 "R68R00E1#0EW" "AX.7/.125 CTRD" 642.01,475 r270 top locked
R19 "R68R00E1#0EW" "AX.7/.125 CTRD" 887,472 r270 top locked
R20 "R10K00D1#0HX0402" 0402/N#2 697.6,88 r0 bottom
R21 "R1K000D1#0HX0402" 0402/N#1 885,-485 r0 bottom
R22 "R1K000D1#0GX0603" 0603/N#1 -21,-862 r180 bottom
R23 "R17K80D1#0HX0402" 0402/N#1 610.01,-585 r0 bottom
R24 "R5K110D1#0GX0603" 0603/N#2 325,-425 r180 bottom
R25 "R10K00D1#0HX0402" 0402/N#1 565,-469 r0 bottom
R26 "R73K20D1#0HX0402" 0402/N#1 880,-420 r0 bottom
R27 "R16K90E0#1AX0805" 0805/N#1 -129,333 r90 top
R27A "R162K0E0#1AX0805" 0805/N#1 358,243 r90 bottom
R28 "R11K50E0#1AX0805" 0805/n 904.6,145 r270 bottom
R29 "R100K0D1#0GX0603" 0603/N#2 974.61,146 r270 bottom
R30 "R11K50E0#1AX0805" 0805/N#1 641,-843 r0 bottom
R31 "R182K0D1#0GX0603" 0603/N#2 630,-763 r270 bottom
R32 "R200K0D1#0HX0402" 0402/N#1 646,-905 r180 bottom
R34 "R100K0D1#0GX0603" 0603/N#2 610.01,-670 r270 bottom
R35 "R61K90D1#0GX0402" 0402/N#1 1034.61,146 r270 bottom
R36 "R49K90D1#0HX0402" 0402/N#1 551,-810 r270 bottom
R39 "R14K70D1#0HX0402" 0402/N#1 1025,247 r180 bottom
R40 "R20K00D1#0HX0402" 0402/N#3 550.01,-730 r270 bottom
R43 "R1K000D1#0HX0402" 0402/N#4 955.01,-910 r90 bottom
R44 "R1K000D1#0HX0402" 0402/N#1 800.01,-910 r90 bottom
R45 "R1K000D1#0HX0402" 0402/N#1 695.01,-610 r90 bottom
R46 "R1K000D1#0HX0402" 0402/N#1 945.01,-601 r90 bottom
R47 "R1K000D1#0HX0402" 0402/N#5 894,-593 r90 bottom
R48 "R1K000D1#0HX0402" 0402/N#1 843,-595 r90 bottom
R49 "R1K000D1#0HX0402" 0402/N#5 785,-557 r90 bottom
R50 "R1K000D1#0HX0402" 0402/N#5 740,-557 r90 bottom
R52 "R100K0D1#0HX0402" 0402/N#1 909.3,-2 r180 bottom
R53 "R412K0D1#0GX0603" 0603/N#2 818,-40 r180 bottom
R56 "R15K00D1#0HX0402" 0402/N#1 664,-685 r90 bottom
R57 "R301K0D1#0HX0402" 0402/N#1 838,-96 r0 bottom
R58 "R499K0D1#0GX0603" 0603/N#2 605,-531 r0 bottom
R59 "R10K00D1#0AX0805" 0805/N#1 395.01,-910 r180 bottom (schematic designator R*59)
R60 "R1K000D1#0HX0402" 0402/N#1 -35,-420 r0 bottom
R61 "R93K10D1#0HX0402" 0402/N#1 295.01,-910 r270 bottom
R62 "R100K0D1#0HX0402" 0402/N#1 450.01,-525 r90 bottom
R63 "R10K00D1#0HX0402" 0402/N#6 465,-743 r270 bottom
R64 "R2K370D1#0HX0402" 0402/N#1 170.01,-355 r270 bottom
R65 "R475K0E0#1AX0805" 0805/N#2 220,-548 r0 bottom
R66 "R1M000M5#0BX0402" 0402/N#1 260,-445 r270 bottom
R67 "R619K0D1#0HX0402" 0402/N#1 196,-685 r0 bottom
R68 "R499K0D1#0GX0603" 0603/N#2 220.01,-625 r180 bottom
R69 "R121R0D1#0BX1206" 1206/N 593,343 r90 bottom
R70 "R6K810D1#0BX1206" 1206/N 688,344 r90 bottom
R71 "R499R0D1#0EX2512" 2512/N 630,785 r270 bottom
R72 "R3K900D5#0DX2010" 2010/N 529,195 r180 bottom
R73 "R4R990M1#0GX0603" 0603/N#2 4,381 r180 bottom
R74 "R4R990M1#0GX0603" 0603/N#2 4,312 r0 bottom
R75 "R4R990M1#0GX0603" 0603/N#2 97,643 r0 bottom
R76 "R90K90D1#0HX0402" 0402/N#1 310,605 r90 bottom
R77 "R412K0D1#0GX0603" 0603/N#2 545,-899 r90 bottom
R80 "R100R0D1#0HX0402" 0402/N#1 -66,344 r90 top
R84 "R1K000D1#0GX0603" 0603/N#1 336,-51 r90 bottom
R86 "R47K50D1#0HX0402" 0402/N#2 500,-16 r180 bottom
R87 "R32K40D1#0HX0402" 0402/N#1 315,64 r90 bottom
R88 "R32K40D1#0HX0402" 0402/N#1 499.6,53 r90 bottom
R89 "R32K40D1#0HX0402" 0402/N#1 611,-26 r0 bottom
R90 "R1K000D1#0HX0402" 0402/N#2 166,-150 r180 bottom
R91 "NOT USED (0402)" 0402/N#2 322,-146 r90 bottom
R92 "R17K80D1#0HX0402" 0402/N#2 313,-224 r270 bottom
R93 "R100K0D1#0HX0402" 0402/N#2 565,-226 r90 bottom
R94 "R1M000M5#0BX0402" 0402/N#2 585,-139 r180 bottom
R95 "0402_JUMPER" 0402/N#2 585,-98 r180 bottom
R96 "R15K00D1#0HX0402" 0402/N#2 499,-446 r0 bottom
R97 "R38K30D1#0GX0603" 0603/N#2 658,-317 r180 bottom
R98 "R200R0D1#0GX0603" 0603/N#2 696,-619 r270 top
TRM1 "TERM832HEX250" TERM832HEX250#1 0,0 r0 top locked
TRM2 "TERM832HEX250" TERM832HEX250#2 900,750 r0 top
U1 "TMN250V_40IX" SO-8-PP/N 506,-619 r0 top
U2 "INA169NA_X" SOT-23-5/N -79,474 r180 top
U3 "AD822ARM_X" MSOP-8/N 804,146 r270 bottom
U4 "LM2902_X" "TSSOP14/N - no FIDS" 527,-839 r180 top
U5 "LMV331_X" SOT-23-5/N 468,-131 r270 bottom
U7 "LMV393_X" MSOP-8/N 95,-575 r270 bottom
U8 "ADC08832_X" MSOP-8/N 895.01,-755 r90 bottom
U9 "ADC08832_X" MSOP-8/N 765,-754 r90 bottom
U10 "LTC1144_X" SO-8/N 223.13,802.13 r180 bottom
U11 "MAX6330_X" SOT-23/N 640,569 r90 bottom

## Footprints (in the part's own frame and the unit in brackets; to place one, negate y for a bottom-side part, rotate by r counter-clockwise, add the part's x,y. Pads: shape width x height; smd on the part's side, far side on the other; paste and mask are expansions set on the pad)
0402/0.60/N [mm] "CAPC1005X60N     GTN 9/22/06"
  rect 0.45x0.65 smd: 1(-0.5,0) 2(0.5,0)
  silkscreen extent -0.51,-0.51 0.51,0.51
0402/N#1 [mm] "RESC1005N"
  rect 0.45x0.65 smd: 1(-0.5,0) 2(0.5,0)
  silkscreen extent -0.51,-0.51 0.51,0.51
0402/N#2 [mm]
  rect 0.45x0.65 smd: 1(-0.5,0.007) 2(0.5,0.007)
  silkscreen extent -0.51,-0.5 0.51,0.51
0402/N#3 [mm] "RESC1005N"
  rect 0.45x0.65 smd: 1(-0.533,0) 2(0.508,0)
  silkscreen extent -0.51,-0.51 0.51,0.51
0402/N#4 [mm] "RESC1005N"
  rect 0.45x0.65 smd: 1(-0.508,0) 2(0.521,0)
  silkscreen extent -0.51,-0.51 0.51,0.51
0402/N#5 [mm] "RESC1005X40N"
  rect 0.45x0.65 smd: 1(-0.508,0) 2(0.508,0)
  silkscreen extent -0.51,-0.51 0.51,0.51
0402/N#6 [mm]
  rect 0.45x0.65 smd: 1(-0.508,0.007) 2(0.508,0.007)
  silkscreen extent -0.51,-0.5 0.51,0.51
0603/0.90/N [mm] "0603 0.90mm high"
  rect 0.6x1 smd: 1(-0.7,0) 2(0.7,0)
  silkscreen extent -0.64,-0.7 0.64,0.7
0603/N#1 [mm]
  rect 0.6x1 smd: 1(-0.7,0.014) 2(0.7,0.014)
  silkscreen extent -0.63,-0.69 0.64,0.71
0603/N#2 [mm] "RESC1608X50N"
  rect 0.6x1 smd: 1(-0.7,0) 2(0.7,0)
  silkscreen extent -0.64,-0.7 0.64,0.7
0805/N#1 [mm] "RESC2012N"
  rect 1.2x1.4 smd: 1(-0.9,0) 2(0.9,0)
  silkscreen extent -0.9,-0.91 0.9,0.91
0805/N#2 [mm]
  rect 1.2x1.4 smd: 1(-0.9,0.007) 2(0.9,0.007)
  silkscreen extent -0.9,-0.9 0.9,0.92
0805/n [mm]
  rect 1.2x1.4 smd: 1(-0.9,0.007) 2(0.9,0.007)
  silkscreen extent -0.9,-0.9 0.9,0.92
1206/N [mm] "RESC3216N"
  rect 1.3x1.8 smd: 1(-1.5,0) 2(1.5,0)
  silkscreen extent -1.5,-1.12 1.5,1.12
1210/N#1 [mm]
  rect 1.3x2.7 smd: 1(-1.45,0) 2(1.45,0)
  silkscreen extent -1.7,-1.6 1.7,1.6
1210/N#2 [mm] "CAPC3225X279N     GTN 9/25/06"
  rect 1.15x2.7 smd: 1(-1.5,0) 2(1.5,0)
  silkscreen extent -1.7,-1.55 1.7,1.55
1812/N [mm]
  rect 1.6x3.4 smd: 1(-2,0) 2(2,0)
  silkscreen extent -2.4,-1.9 2.4,1.9
1825/2.18/N [mm] "CAPC4564X218N     GTN 9/25/06"
  rect 1.2x6.65 smd: 1(-2.15,0) 2(2.15,0)
  silkscreen extent -2.4,-3.65 2.4,3.65
2010/N [mm]
  rect 1.4x2.7 smd: 1(-2.3,0) 2(2.3,0)
  silkscreen extent -2.51,-1.6 2.51,1.6
2512/N [mm]
  rect 1.3x3.5 smd: 1(-2.95,0) 2(2.95,0)
  silkscreen extent -3.25,-2 3.25,2
3528/N [mm] "CAPMP3528N   CASE B"
  rect 2x2.2 smd: 1(1.5,0) 2(-1.5,0)
  silkscreen extent -1.4,-1.6 1.4,1.6
"AX.7/.125 CTRD" [mil]
  round 48 hole 28: 1(0,0) 2(700,0)
  silkscreen extent 44,-63 657,63
AX.83/.158FL [mil]
  round 80 hole 50: 1(0,0) 2(830,0)
  silkscreen extent 48,-80 782,80
DO-214AB/N [mil] "DO-214AB/N GTN 9/8/06"
  rect 87x125 smd: 1(134,0) 2(-138,0)
  silkscreen extent -140,-130 140,130
FIDUCIAL_X#1 [mil]
  round 40 all layers, no hole: FD?(0,0)
FIDUCIAL_X#2 [mil]
  round 40 all layers, no hole: FD5(0,0)
FIDUCIAL_X#3 [mil]
  round 40 all layers, no hole: FD6(0,0)
MLL41/N [mm] "DIOMELF5025N(TO-213AB)     GTN 9/8/06"
  rect 1.3x2.8 smd: 1(-2.35,0)
  rect 1.34x2.8 smd: 2(2.35,0)
  silkscreen extent -2.6,-1.75 2.63,1.75
MSOP-8/N [mm]
  rect 1.55x0.45 smd: 1(-2.15,0.953) 2(-2.15,0.318) 3(-2.15,-0.317) 4(-2.15,-0.952) 5(2.15,-0.953) 6(2.15,-0.318) 7(2.15,0.317) 8(2.15,0.952)
  silkscreen extent -1.27,-1.55 1.27,1.55
SC-79/N [mil] "SC-79/N GTN 9/8/06"
  rect 20x39 smd: 1(0,28.5) 2(0,-28.5)
  silkscreen extent -23,-25 23,25
SIP1 [mil]
  round 62 hole 36: 1(0,0)
  silkscreen extent -50,-50 50,50
SIP7 [mil]
  rect 62x62 / inner round 62 / far side rect 62x62 hole 36: 1(0,0)
  round 62 hole 36: 2(100,0) 3(200,0) 4(300,0) 5(400,0) 6(500,0) 7(600,0)
  silkscreen extent -50,-50 650,50
SMA/N [mil] "SMA/N GTN 9/8/06"
  rect 85x85 smd: 1(90.5,0) 2(-90.5,0)
  silkscreen extent -112,-66 112,66
SO-8-PP/N [mm] "SO-8-PP/N GTN 9/22/06"
  rect 1.2x0.5 smd: 1(-3.25,1.875) 2(-3.25,0.605)
  rect 1.15x0.5 smd: 3(-3.25,-0.665) 5(3.25,-1.935) 6(3.25,-0.665) 7(3.25,0.605) 8(3.25,1.875)
  rect 1.2x0.61 smd: 4(-3.25,-1.905)
  rect 1.15x5.08 smd: 5(-0.65,0)
  rect 3.9x4.1 smd: 5(0.725,0)
  silkscreen extent -3.82,-2.7 3.1,2.78
SO-8/N [mm] "SO-8/N GTN 9/21/06"
  rect 1.55x0.6 smd: 1(-2.7,1.905) 2(-2.7,0.635) 3(-2.7,-0.635) 4(-2.7,-1.905) 5(2.7,-1.905) 6(2.7,-0.635) 7(2.7,0.635) 8(2.7,1.905)
  silkscreen extent -1.7,-2.5 1.7,2.5
SOT-23-5/N [mil] "SOT-23-5/N GTN 9/11/06"
  rect 24x41 smd: 1(34,53) 2(0.5,53) 3(-34,53) 4(-34,-53) 5(34,-53)
  silkscreen extent -60,-40 60,35
SOT-23-6/N [mm] "SOT-23-6/N GTN 9/19/06"
  rect 0.4x0.9 smd: 1(0.953,1.1) 2(0.013,1.1) 3(-0.953,1.1) 4(-0.953,-1.1) 5(0.013,-1.1) 6(0.953,-1.1)
  silkscreen extent -1.59,-1.09 1.59,1.07
SOT-23/N [mm] "SOT95P240-3N"
  rect 0.65x1.3 smd: 1(-0.95,-1) 2(0.95,-1) 3(0,1)
  silkscreen extent -1.47,-0.7 1.45,0.7
TERM832HEX250#1 [mil]
  round 310 hole 234: 1(0,0)
TERM832HEX250#2 [mil]
  oval 310x330 / inner round 310 / far side round 310 hole 234: 1(0,0)
TP-100#1 [mil] ".076 Dia hole for SMT Pins"
  round 110 / inner round 110 / far side round 150 hole 85: 1(0,0)
  silkscreen extent -55,-55 55,55
TP-100#2 [mil] ".076 Dia hole for SMT Pins"
  round 92 / inner round 92 / far side oval 150x92 hole 72: 1(0,0)
  silkscreen extent -55,-55 55,55
TP-100#3 [mil] ".076 Dia hole for SMT Pins"
  round 95 / inner round 95 / far side oval 150x95 hole 85: 1(0,0)
  silkscreen extent -55,-55 55,55
TP-100#4 [mil] ".076 Dia hole for SMT Pins"
  round 110 / inner round 110 / far side oval 150x120 hole 85: 1(0,0)
  silkscreen extent -55,-55 55,55
TP-100#5 [mil] ".076 Dia hole for SMT Pins"
  round 110 / inner round 110 / far side oval 120x150 hole 85: 1(0,0)
  silkscreen extent -55,-55 55,55
TP-100#6 [mil] ".076 Dia hole for SMT Pins"
  round 110 / inner round 110 / far side oval 135x110 hole 85: 1(0,0)
  silkscreen extent -55,-55 55,55
"TSSOP14/N - no FIDS" [mm] "TSOP65P640X110-14N     GTN 9/22.06"
  rect 1.45x0.45 smd: 1(-2.95,1.95) 2(-2.95,1.3) 3(-2.95,0.65) 4(-2.95,0) 5(-2.95,-0.65) 6(-2.95,-1.3) 7(-2.95,-1.95) 8(2.95,-1.95) 9(2.95,-1.3) 10(2.95,-0.65) 11(2.95,0) 12(2.95,0.65) 13(2.95,1.3) 14(2.95,1.95)
  silkscreen extent -2,-2.55 2,2.55

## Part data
C3: "CAPACITOR, CERAMIC, .022UF 5%, X7R, 100V"
C4 C23: "CAPACITOR, CERAMIC, 1.0UF 10%, X7R, 100V"
C5 C22: "CAPACITOR, CERAMIC, 0.1UF, 10%, X7R, 50V, 0805"
C6: library part 104-50V-10CX1206, "CAPACITOR, CERAMIC, 0.1UF 10%, X7R, 50V"
C7 C8: "CAPACITOR, CERAMIC, 2.2UF 10%, X7R, 16V"
C9 C10 C11 C28: "CAPACITOR, CERAMIC, 0.1UF, 1%, X7R, 10V, 0402"
C13: library part 103-10V-1#CX0402, "CAPACITOR, CERAMIC, 0.01UF, 1%, X7R, 10V, 0402"
C14 C15: "CAPACITOR, CERAMIC, 100PF 5%, COG, 10V"
C16: library part 472-50V-10CX0402, "CAPACITOR, CERAMIC, 4700pF, 1%, X7R, 50V, 0402"
C18 C19: "CAPACITOR, CERAMIC, 1000pF 5%, X7R, 25V, 0402"
C20 C21: "CAPACITOR, TANTALUM, 4.7UF 10%, 20V, 3528"
C24 C25 C26 C27: library part 335-35V-10TX3528, "CAPACITOR, TANTALUM, 3.3uF, 10%, 35V, 3528"
C29: library part 104-50V-10CX0805, "CAPACITOR, CERAMIC, 0.1UF, 10%, X7R, 50V, 0805"
C30: library part 104-50V-10CX0603, "CAPACITOR, CERAMIC, 0.1UF 10%, X7R, 50V, 0603"
C31 C32: "CAPACITOR, CERAMIC, 0.47UF 10%, X7R, 50V"
C33: "CAPACITOR, CERAMIC, 0.01UF, 1%, X7R, 10V, 0402"
CR3 CR4 CR5 CR6 CR7 CR8 CR10: "DIODE, SWITCHING, 80V"
CR11 CR12: "DIODE, RECTIFIER, 40V, 1A, MELF"
CR13: library part Z36V0U1K50ZX, "DIODE, TRANSZORB, 36V, 1500 WATTS"
CR14: "DIODE, RECTIFIER, 70V"
CR15 CR16 CR25: library part Z12V0UW300JX, "ZENER, DIODE, 12V"
CR17: "DIODE, SCHOTTKY, 30V, D30V0_I15S_X, SSMINI2-F1"
CR18 CR19: library part D70V0SI015S_X, "DIODE, SHOTTKY, DUAL, SERIES PAIR, 70V"
CR20: "ZENER, DIODE, 12V, 1W, SMA"
CR23: "ZENER, DIODE, 20V"
CR26 CR27: "DIODE,  DUAL, SERIES PAIR, 75V"
CR29: "ZENER, DIODE, 12V"
E1 E2 E3 E4 E5 E6 E7: library part "1P ST PRESS FIT PIN", "PIN, 1 POS, ST, PRESS FIT, 0.032 HOLE"
FD1 FD2 FD3 FD4 FD5 FD6 FD7 FD8: library part FID_TOP, "FIDUCIAL, .040DIA W/ .120DIA CLEARANCE (TOP ONLY)"
FD9 FD10: library part FID_BOT, "FIDUCIAL, .040DIA W/ .120DIA CLEARANCE (BOTTOM ONLY)"
FL1 FL2: "THERMAL CUTOFF,152degCMax, 25A@250VAC, THERMTROL G5A01152"
P1 P2: library part "7P ST LHDR 100", "HEADER, 7 PIN, ST, 0.100 CTRS, DOUBLE SIDED"
P3 P4: library part "1P ST HDR", "HEADER, 1 PIN, ST"
Q5 Q6 Q7 Q9: "TRANSISTOR, NPN, 300V 500mA, GAIN = 240"
Q8: "TRANSISTOR, PNP, 300V, SOT-23"
Q10 Q11: "TRANSISTOR, NPN, DUAL 50V"
R5 R29 R34: "RESISTOR, 100.0K OHMS, 1%, 0603"
R6: "RESISTOR, 20K OHM, 1%, 100 PPM, 0402"
R7 R8 R10 R12 R15: library part R100K0D1#0HX0402, "RESISTOR, 100.0K OHMS, 1%, 0402"
R9: library part R100K0D1#0AX0805
R11 R13 R14: "RESISTOR, 100.0K OHMS, 1%, 0402"
R16 R97: "RESISTOR, 38.3K OHM, 1%, 100 PPM, 0603"
R20: library part R10K00D1#0GX0603, "RESISTOR, 10K OHM, 1%, 100 PPM, 0603"
R21 R22 R23: library part R10K00D1#0HX0402, "RESISTOR, 10K OHM, 1%, 100 PPM, 0402"
R24: library part R1K000M1#0GX0603, "RESISTOR, 1k OHMS, 1%, 300 PPM, 0603"
R25: library part R2K370D1#0HX0402, "RESISTOR, 2.37K, 1%, 100 PPM, 0402"
R26: "RESISTOR, 73.2K OHM, 1%, 100 PPM, 0402"
R27: library part R20K00E0#1AX, "RESISTOR, 20K, .1%, 25 PPM, 0805"
R27A: "RESISTOR, THIN FILM 162K, 0.1%, 25 PPM, 0805"
R30 R31 R32: library part R100K0D1#0GX0603, "RESISTOR, 100.0K OHMS, 1%, 0603"
R35 R57 R90 R92 R95: library part R49K90D1#0HX0402, "RESISTOR, 49.9K OHM, 1%, 100 PPM, 0402"
R36: "RESISTOR, 49.9K OHM, 1%, 100 PPM, 0402"
R39 R40 R91 R93 R94: library part R1K000D1#0HX0402, "RESISTOR, 1K OHM, 1%, 100 PPM, 0402"
R43 R44 R45 R46 R47 R48 R49 R50: "RESISTOR, 1K OHM, 1%, 100 PPM, 0402"
R52 R56: library part R374K0D1#0HX0402, "RESISTOR, 374K OHMS, 1%, 0402"
R53 R77: library part R348K0D1#0GX0603, "RESISTOR, 348.0K OHMS, 1%, 0603"
R58: library part R90K90D1#0GX0603, "RESISTOR, 90.9K OHMS, 1%, 0603"
R59: library part R15K60E0#1AX0805, "RESISTOR, THIN FILM 15.6K, 0.1%, 25 PPM, 0805"
R60: library part R22K10D1#0BX1206, "RESISTOR, 22.1K, 1%, 100 PPM, 1206"
R61 R62: library part R88K70D1#0HX0402, "RESISTOR, 88.7K OHM, 1%, 100 PPM, 0402"
R63 R64 R65: library part R200K0D1#0HX0402, "RESISTOR, 200.0K OHMS, 1%, 0402"
R66 R67 R68: library part R475K0D1#0HX0402, "RESISTOR, 475K OHMS, 1%, 0402"
R69: library part R121K0E0#1AX0805
R70: library part R68K10D1#0AX0805
R71: library part R2K000D5#0EX2512, "RESISTOR, R2K000D5#0EX2512"
R72: library part R2K000D1#0EX2010, "RESISTOR, 2 K OHM, 1%, 100 PPM, 2010"
R73 R74 R75: "RESISTOR, 4.99 OHMS, 1%, 300 PPM, 0603"
R76: "RESISTOR,90.9K OHM, 1%, 100 PPM, 0402"
R80: "RESISTOR, 100.0 OHMS, 1%, 0402"
R84: "RESISTOR, 1k OHMS, 1%, 100 PPM, 0603"
R86: "RESISTOR, 47.5K OHM, 1%, 100 PPM, 0402"
R87 R88 R89: library part R30K10E0#1HX0402, "RESISTOR, THIN FILM 30.1K OHMS, 0.1%, 0402"
R96: "RESISTOR, 15K OHM, 1%, 100 PPM, 0402"
R98: library part R182K0D1#0GX0603, "RESISTOR, 182.0K OHMS, 1%, 0603"
TRM1 TRM2: "TERMINAL 8-32 SCREW W/ .250DIA HEX"
U1: library part FDS5670_X, "IC, 60V N-CHANNEL MOSFET"
U2: "IC, CURRENT SHUNT MONITOR, SOT-23-5"
U3: "IC, LOW POWER FET- INPUT OP AMPS, MSOP-8"
U5: "IC, COMPARITOR, LOW VOLTAGE, SOT23-5"
U7: "IC, DUAL OPEN DRAIN OUTPUT COMPARATOR"
U8 U9: "IC, CMOS A/D CONVERTER"
U10: library part ICL7660_X, "IC,  CMOS Voltage Converter, SO-8"
U11: "IC,  SHUNT VOLTAGE REGULATOR, SMT"

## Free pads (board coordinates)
  round 110 hole 125 unplated: 0(739.5,-183.5)
  round 125 hole 125 unplated: 1(-530,-805) 1(-530,795) 1(1430,-805) 1(1430,795)
  round 6 on Mech5: 1(-167.12,215.09) 1(-167.12,835.09) 1(-3.34,215.09) 1(-3.34,835.09) 1(142.88,-49.91) 1(142.88,125.09) 1(217.88,-749.91) 1(306.66,-49.91) 1(306.66,125.09) 1(367.88,625.09) 1(367.88,800.09) 1(531.66,625.09) 1(531.66,800.09)
  round 5 on Mech6: 1(-137.73,0.09) 1(137.27,0.09) 1(554.77,493.09) 1(617.77,430.09)
  round 5 on Mech5: 1(-137.36,-0.91)
  round 125 on Mech5: 1(-85.23,215.09) 1(-85.23,835.09) 1(224.77,-49.91) 1(224.77,125.09) 1(299.77,-749.91) 1(449.77,625.09) 1(449.77,800.09)
  round 125 on Mech6: 1(429.9,816.73)
  round 24 hole 12: 1(805,-736)
  round 16 hole 8: 2(-142,274) 2(-130,378.87) 2(-118,755) 2(-108,-917) 2(-92,513) 2(-80,445) 2(-61,699) 2(-44.99,-370) 2(-36,590) 2(-15,-416.5) 2(-12,273) 2(-1.5,-508) 2(-0.3,-320) 2(9.5,-911.5) 2(10,-621) 2(18.01,-804) 2(21,-498.5) 2(52.01,-865) 2(53,-260) 2(74.01,-580) 2(82.5,-523) 2(107.51,-481) 2(114,727) 2(124,616) 2(127.41,-207.63) 2(133,-706) 2(144,-776) 2(159,-159) 2(169.26,511) 2(170.01,-335.31) 2(175.01,-417) 2(183,-594) 2(186,861.5) 2(188.47,-867) 2(210.5,-684) 2(215,-481) 2(220.01,-279.37) 2(234,-630) 2(234,-545.5) 2(257.41,-201) 2(265.01,-473) 2(265.01,-417) 2(269,-303) 2(270,-885) 2(308,-164) 2(308,243) 2(312.73,-243.69) 2(313,-420) 2(321,661) 2(324,-99) 2(339.01,-860) 2(359,-809) 2(361,-838) 2(370.6,16) 2(375,-715) 2(408.6,16) 2(408.6,110) 2(419,-744) 2(423,-412) 2(438.5,-670) 2(441,-594) 2(457,-376) 2(467,-843) 2(472,-819) 2(479.25,-36.85) 2(489.01,-872) 2(490.01,-927.56) 2(495,-735) 2(496,-482) 2(520,-517.5) 2(533,-127) 2(553,-832) 2(555,-873) 2(565,133) 2(567,-422) 2(568.01,-646) 2(578,-735) 2(580,-794) 2(583.5,-71.5) 2(586.63,606.4) 2(592,45) 2(595,-860.5) 2(596,-171) 2(619,-890) 2(620,-406) 2(631,-317) 2(644,670) 2(663,-620) 2(665,-670) 2(666,569) 2(672,-519) 2(672.01,-864) 2(675,-712) 2(681.62,208) 2(694,-33) 2(694,432) 2(698.5,-526.5) 2(699,-70) 2(725.43,52) 2(727.51,-849) 2(740,-927) 2(752.5,-806) 2(777.5,-808) 2(796.5,405.5) 2(808.61,276) 2(808.62,178) 2(819.6,119) 2(820,-570) 2(839.5,-469.5) 2(841.51,226) 2(855.33,-424) 2(857.51,-849) 2(874.6,64) 2(880,-926) 2(882.5,-808.5) 2(907.5,-808.5) 2(909.7,-41) 2(929.6,352) 2(933,-713) 2(958.01,-63) 2(978,-624) 2(1014.61,-12) 2(1015.6,-136) 2(1024.62,54) 2(1031.61,311.57) 2(1035.01,126) 2(1040.01,-78) 2(1055,466)
  oval 16x14 hole 8: 2(500,-899) 2(525,-899)
  round 10 hole 10 unplated: 4(-202,-800) 4(-202,-620) 4(-202,-95) 4(-202,85) 4(-202,625) 4(-202,805) 4(-196.99,-785) 4(-196.99,-770) 4(-196.99,-755) 4(-196.99,-740) 4(-196.99,-725) 4(-196.99,-710) 4(-196.99,-695) 4(-196.99,-680) 4(-196.99,-665) 4(-196.99,-650) 4(-196.99,-635) 4(-194.99,-80) 4(-194.99,-65) 4(-194.99,-50) 4(-194.99,-35) 4(-194.99,-20) 4(-194.99,-5) 4(-194.99,10) 4(-194.99,25) 4(-194.99,40) 4(-194.99,55) 4(-194.99,70) 4(-194.99,640) 4(-194.99,655) 4(-194.99,670) 4(-194.99,685) 4(-194.99,700) 4(-194.99,715) 4(-194.99,730) 4(-194.99,745) 4(-194.99,760) 4(-194.99,775) 4(-194.99,790) 4(1090.01,-785) 4(1090.01,-770) 4(1090.01,-755) 4(1090.01,-740) 4(1090.01,-725) 4(1090.01,-710) 4(1090.01,-695) 4(1090.01,-680) 4(1090.01,-665) 4(1090.01,-650) 4(1090.01,-635) 4(1090.01,-80) 4(1090.01,-65) 4(1090.01,-50) 4(1090.01,-35) 4(1090.01,-20) 4(1090.01,-5) 4(1090.01,10) 4(1090.01,25) 4(1090.01,40) 4(1090.01,55) 4(1090.01,70) 4(1090.01,640) 4(1090.01,655) 4(1090.01,670) 4(1090.01,685) 4(1090.01,700) 4(1090.01,715) 4(1090.01,730) 4(1090.01,745) 4(1090.01,760) 4(1090.01,775) 4(1090.01,790) 4(1097,-800) 4(1097,-620) 4(1097,-95) 4(1097,85) 4(1097,625) 4(1097,805)
  round 36 hole 16: 5(-150,0) 5(-109,104) 5(-103,-110) 5(-2,-150) 5(5,150) 5(104,108) 5(108,-104) 5(148,17) 5(750,750) 5(778,838) 5(791,647) 5(900,600) 5(900,900) 5(1011,852) 5(1012,649) 5(1050,750)
  oct 25x25 smd far side: 8(-162,301) 8(-154,140) 8(-150,765) 8(-85,-893) 8(-80,415) 8(-75,-305) 8(-69.99,-500) 8(-29.99,-515) 8(15,210) 8(15,820) 8(15.01,-420) 8(25,760) 8(27.5,-470) 8(28,-662.5) 8(54,-926.5) 8(85,-435) 8(90,-190) 8(120,565) 8(175.01,675) 8(185.01,-305) 8(208,-915) 8(220.01,-435) 8(262.5,558) 8(275,660) 8(281.01,-668) 8(285,-125.31) 8(309.01,-312) 8(315,10) 8(330,-830) 8(330,-275) 8(370,150) 8(385,-775.5) 8(387.01,-455) 8(390,-742) 8(400.44,401.57) 8(425,-273) 8(437,-860) 8(450.01,-475) 8(475,900) 8(490,110) 8(516,-760) 8(520,275) 8(565,-615) 8(565.27,-175) 8(580.01,450) 8(583.5,-765.5) 8(585,-891.5) 8(597,-925) 8(635,-145) 8(635,-90) 8(644,-180) 8(659.5,-396.5) 8(670,-540) 8(676.5,-740.5) 8(677,-793.5) 8(698,-665) 8(715,5) 8(725,635) 8(725,875) 8(729,-610) 8(754.61,284) 8(765.01,-910) 8(785,-85) 8(795,-615) 8(802,-432.5) 8(819.61,9) 8(830,-395) 8(879.61,414) 8(890,-96) 8(904.61,225) 8(930,-455) 8(939.61,272) 8(940,-190) 8(965,-850) 8(969,-660) 8(970,-300) 8(974.61,407) 8(980,-700) 8(980,-595) 8(985,-136) 8(989.61,-66) 8(989.61,9) 8(995,-795) 8(1000,-892) 8(1024.61,94) 8(1034.61,200) 8(1055,-900) 8(1055,435)
  oct 25x25 hole 8: 8(762,-606)
  oct 21x25 smd far side: 8(830.01,-665)
  round 24 / inner round 24 / far side oct 24x24 hole 12: 9(-95,-790)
